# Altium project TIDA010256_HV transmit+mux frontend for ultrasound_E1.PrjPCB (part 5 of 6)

## Sheet 21_TX7516_PartBPinout.SchDoc
size 431 x 279 mm; Date: Not shown in title block; ApprovedBy: Not shown in title block; CheckedBy: Not shown in title block; Author: Not shown in title block; CompanyName: Not shown in title block; Engineer: Not shown in title block; Organization: Not shown in title block; Address1: Not shown in title block; Address2: Not shown in title block; Address3: Not shown in title block; Address4: Not shown in title block; DocumentNumber: 13; Revision: Use project parameter SCH_Rev; SheetNumber: 13; SheetTotal: 18; PageSetup: Record=PageOptions¦CenterHorizontal=True¦CenterVertical=True¦PrintScale=1.00¦XCorrection=1.00¦YCorrection=1.00¦PrintKind=0¦BorderSize=5000000¦LeftOffset=0¦BottomOffset=0¦Orientation=2¦PaperLength=1000¦PaperWidth=1000¦Scale=100¦PaperSource=15¦PrintQuality=600¦MediaType=1¦DitherType=10¦PaperKind=Letter¦PrintScaleMode=1
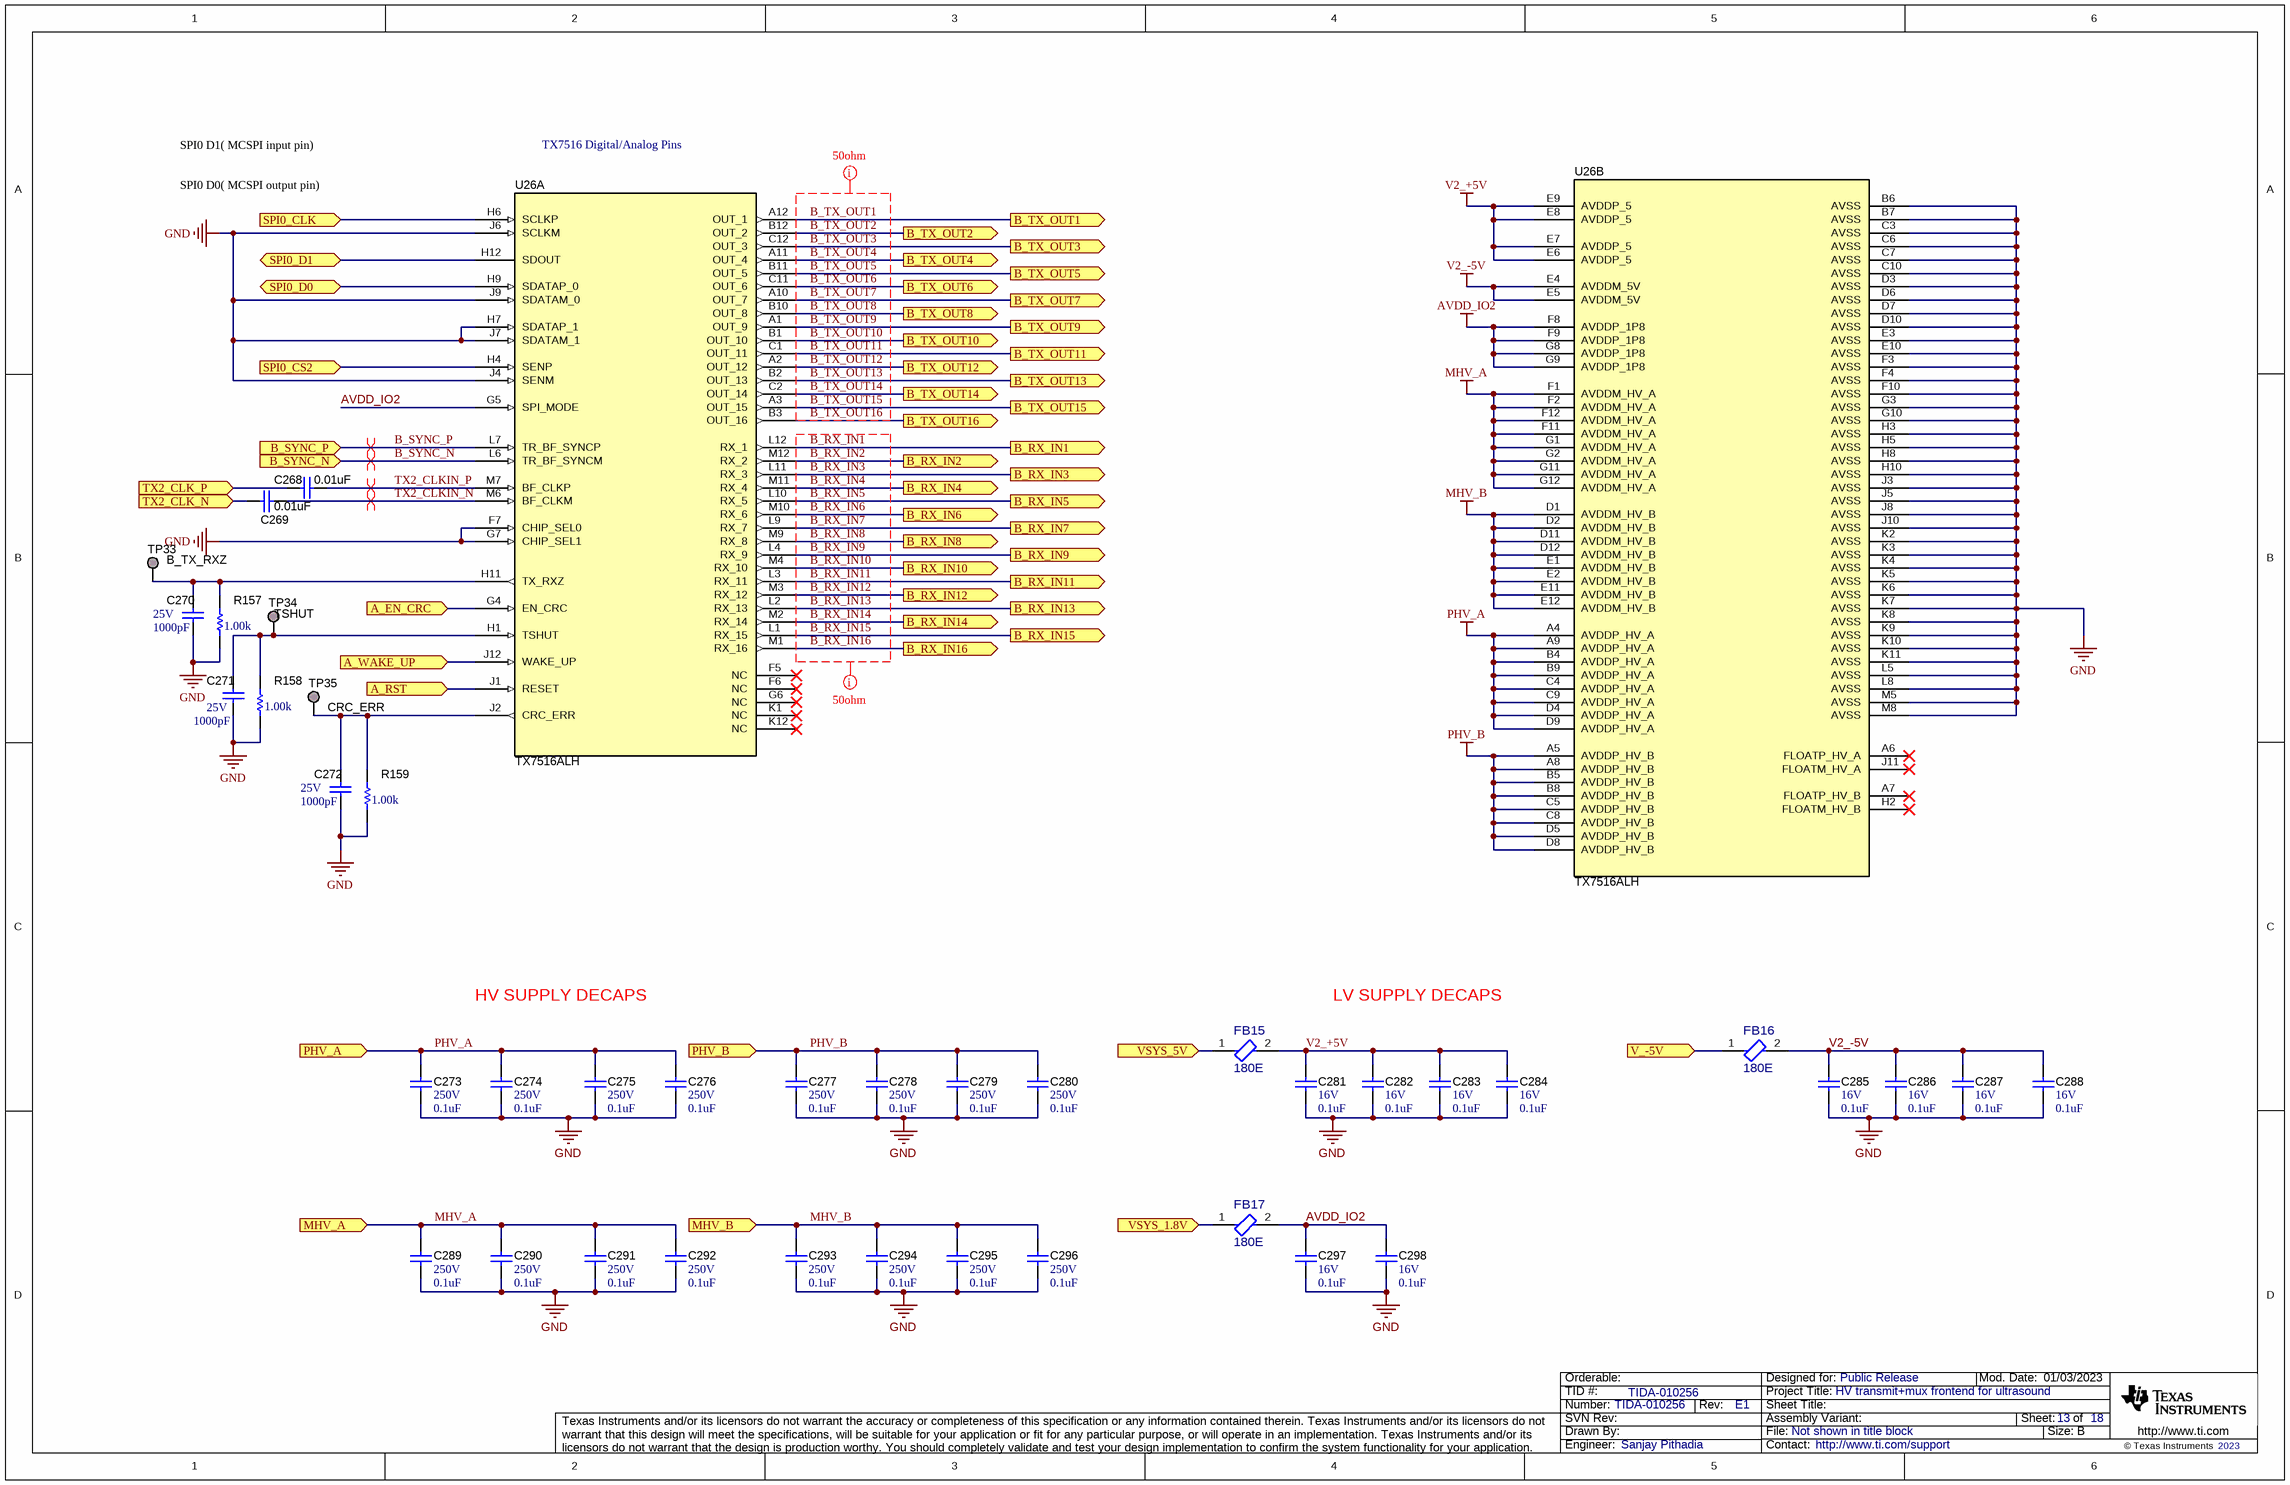
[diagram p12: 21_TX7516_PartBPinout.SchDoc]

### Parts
C268  ValueDisplayed: 0.01uF  [0402_065]  (hidden comment: 520L103KT16T)
C269  ValueDisplayed: 0.01uF  [0402_065]  (hidden comment: 520L103KT16T)
C270  VDC_V: 25V  ValueDisplayed: 1000pF  [0603]  (hidden comment: C0603C102K3GACTU)
C271  VDC_V: 25V  ValueDisplayed: 1000pF  [0603]  (hidden comment: C0603C102K3GACTU)
C272  VDC_V: 25V  ValueDisplayed: 1000pF  [0603]  (hidden comment: C0603C102K3GACTU)
C273  VDC_V: 250V  ValueDisplayed: 0.1uF  [0805_HV]  (hidden comment: C2012X7T2E104K125AA)
C274  VDC_V: 250V  ValueDisplayed: 0.1uF  [0805_HV]  (hidden comment: C2012X7T2E104K125AA)
C275  VDC_V: 250V  ValueDisplayed: 0.1uF  [0805_HV]  (hidden comment: C2012X7T2E104K125AA)
C276  VDC_V: 250V  ValueDisplayed: 0.1uF  [0805_HV]  (hidden comment: C2012X7T2E104K125AA)
C277  VDC_V: 250V  ValueDisplayed: 0.1uF  [0805_HV]  (hidden comment: C2012X7T2E104K125AA)
C278  VDC_V: 250V  ValueDisplayed: 0.1uF  [0805_HV]  (hidden comment: C2012X7T2E104K125AA)
C279  VDC_V: 250V  ValueDisplayed: 0.1uF  [0805_HV]  (hidden comment: C2012X7T2E104K125AA)
C280  VDC_V: 250V  ValueDisplayed: 0.1uF  [0805_HV]  (hidden comment: C2012X7T2E104K125AA)
C281  VDC_V: 16V  ValueDisplayed: 0.1uF  [0201_033]  (hidden comment: C0603X6S1C104K030BC)
C282  VDC_V: 16V  ValueDisplayed: 0.1uF  [0201_033]  (hidden comment: C0603X6S1C104K030BC)
C283  VDC_V: 16V  ValueDisplayed: 0.1uF  [0201_033]  (hidden comment: C0603X6S1C104K030BC)
C284  VDC_V: 16V  ValueDisplayed: 0.1uF  [0201_033]  (hidden comment: C0603X6S1C104K030BC)
C285  VDC_V: 16V  ValueDisplayed: 0.1uF  [0201_033]  (hidden comment: C0603X6S1C104K030BC)
C286  VDC_V: 16V  ValueDisplayed: 0.1uF  [0201_033]  (hidden comment: C0603X6S1C104K030BC)
C287  VDC_V: 16V  ValueDisplayed: 0.1uF  [0201_033]  (hidden comment: C0603X6S1C104K030BC)
C288  VDC_V: 16V  ValueDisplayed: 0.1uF  [0201_033]  (hidden comment: C0603X6S1C104K030BC)
C289  VDC_V: 250V  ValueDisplayed: 0.1uF  [0805_HV]  (hidden comment: C2012X7T2E104K125AA)
C290  VDC_V: 250V  ValueDisplayed: 0.1uF  [0805_HV]  (hidden comment: C2012X7T2E104K125AA)
C291  VDC_V: 250V  ValueDisplayed: 0.1uF  [0805_HV]  (hidden comment: C2012X7T2E104K125AA)
C292  VDC_V: 250V  ValueDisplayed: 0.1uF  [0805_HV]  (hidden comment: C2012X7T2E104K125AA)
C293  VDC_V: 250V  ValueDisplayed: 0.1uF  [0805_HV]  (hidden comment: C2012X7T2E104K125AA)
C294  VDC_V: 250V  ValueDisplayed: 0.1uF  [0805_HV]  (hidden comment: C2012X7T2E104K125AA)
C295  VDC_V: 250V  ValueDisplayed: 0.1uF  [0805_HV]  (hidden comment: C2012X7T2E104K125AA)
C296  VDC_V: 250V  ValueDisplayed: 0.1uF  [0805_HV]  (hidden comment: C2012X7T2E104K125AA)
C297  VDC_V: 16V  ValueDisplayed: 0.1uF  [0201_033]  (hidden comment: C0603X6S1C104K030BC)
C298  VDC_V: 16V  ValueDisplayed: 0.1uF  [0201_033]  (hidden comment: C0603X6S1C104K030BC)
FB15  180E  [FP-MPZ1608S181ATAH0_0603-MFG]
FB16  180E  [FP-MPZ1608S181ATAH0_0603-MFG]
FB17  180E  [FP-MPZ1608S181ATAH0_0603-MFG]
R157  ValueDisplayed: 1.00k  [0603]  (hidden comment: RC0603FR-071KL)
R158  ValueDisplayed: 1.00k  [0603]  (hidden comment: RC0603FR-071KL)
R159  ValueDisplayed: 1.00k  [0603]  (hidden comment: RC0603FR-071KL)
TP33  B_TX_RXZ  [TP_SM_1MM]  (no BOM)
TP34  TSHUT  [TP_SM_1MM]  (no BOM)
TP35  CRC_ERR  [TP_SM_1MM]  (no BOM)
U26  TX7516ALH  [ALH0144A]  (parts A,B of 2)

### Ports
A_EN_CRC (in), A_RST (in), A_WAKE_UP (in), B_RX_IN1 (out), B_RX_IN2 (out), B_RX_IN3 (out), B_RX_IN4 (out), B_RX_IN5 (out), B_RX_IN6 (out), B_RX_IN7 (out), B_RX_IN8 (out), B_RX_IN9 (out), B_RX_IN10 (out), B_RX_IN11 (out), B_RX_IN12 (out), B_RX_IN13 (out), B_RX_IN14 (out), B_RX_IN15 (out), B_RX_IN16 (out), B_SYNC_N (in), B_SYNC_P (in), B_TX_OUT1 (out), B_TX_OUT2 (out), B_TX_OUT3 (out), B_TX_OUT4 (out), B_TX_OUT5 (out), B_TX_OUT6 (out), B_TX_OUT7 (out), B_TX_OUT8 (out), B_TX_OUT9 (out), B_TX_OUT10 (out), B_TX_OUT11 (out), B_TX_OUT12 (out), B_TX_OUT13 (out), B_TX_OUT14 (out), B_TX_OUT15 (out), B_TX_OUT16 (out), MHV_A (in), MHV_B (in), PHV_A (in), PHV_B (in), SPI0_CLK (in), SPI0_CS2 (in), SPI0_D0 (bidir), SPI0_D1 (bidir), TX2_CLK_N (in), TX2_CLK_P (in), V_-5V (in), VSYS_1.8V (in), VSYS_5V (in)

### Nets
AVDD_IO2: C297.1 C298.1 FB17.2 U26.F8(AVDDP_1P8) U26.F9(AVDDP_1P8) U26.G5(SPI_MODE) U26.G8(AVDDP_1P8) U26.G9(AVDDP_1P8)
GND: C270.2 C271.2 C272.2 C273.2 C274.2 C275.2 C276.2 C277.2 C278.2 C279.2 C280.2 C281.2 C282.2 C283.2 C284.2 C285.2 C286.2 C287.2 C288.2 C289.2 C290.2 C291.2 C292.2 C293.2 C294.2 C295.2 C296.2 C297.2 C298.2 R157.1 R158.1 R159.1 U26.B6(AVSS) U26.B7(AVSS) U26.C3(AVSS) U26.C6(AVSS) U26.C7(AVSS) U26.C10(AVSS) U26.D3(AVSS) U26.D6(AVSS) U26.D7(AVSS) U26.D10(AVSS) U26.E3(AVSS) U26.E10(AVSS) U26.F3(AVSS) U26.F4(AVSS) U26.F7(CHIP_SEL0) U26.F10(AVSS) U26.G3(AVSS) U26.G7(CHIP_SEL1) U26.G10(AVSS) U26.H3(AVSS) U26.H5(AVSS) U26.H7(SDATAP_1) U26.H8(AVSS) U26.H10(AVSS) U26.J3(AVSS) U26.J4(SENM) U26.J5(AVSS) U26.J6(SCLKM) U26.J7(SDATAM_1) U26.J8(AVSS) U26.J9(SDATAM_0) U26.J10(AVSS) U26.K2(AVSS) U26.K3(AVSS) U26.K4(AVSS) U26.K5(AVSS) U26.K6(AVSS) U26.K7(AVSS) U26.K8(AVSS) U26.K9(AVSS) U26.K10(AVSS) U26.K11(AVSS) U26.L5(AVSS) U26.L8(AVSS) U26.M5(AVSS) U26.M8(AVSS)
MHV_A: C289.1 C290.1 C291.1 C292.1 U26.F1(AVDDM_HV_A) U26.F2(AVDDM_HV_A) U26.F11(AVDDM_HV_A) U26.F12(AVDDM_HV_A) U26.G1(AVDDM_HV_A) U26.G2(AVDDM_HV_A) U26.G11(AVDDM_HV_A) U26.G12(AVDDM_HV_A) ; port MHV_A
MHV_B: C293.1 C294.1 C295.1 C296.1 U26.D1(AVDDM_HV_B) U26.D2(AVDDM_HV_B) U26.D11(AVDDM_HV_B) U26.D12(AVDDM_HV_B) U26.E1(AVDDM_HV_B) U26.E2(AVDDM_HV_B) U26.E11(AVDDM_HV_B) U26.E12(AVDDM_HV_B) ; port MHV_B
PHV_A: C273.1 C274.1 C275.1 C276.1 U26.A4(AVDDP_HV_A) U26.A9(AVDDP_HV_A) U26.B4(AVDDP_HV_A) U26.B9(AVDDP_HV_A) U26.C4(AVDDP_HV_A) U26.C9(AVDDP_HV_A) U26.D4(AVDDP_HV_A) U26.D9(AVDDP_HV_A) ; port PHV_A
PHV_B: C277.1 C278.1 C279.1 C280.1 U26.A5(AVDDP_HV_B) U26.A8(AVDDP_HV_B) U26.B5(AVDDP_HV_B) U26.B8(AVDDP_HV_B) U26.C5(AVDDP_HV_B) U26.C8(AVDDP_HV_B) U26.D5(AVDDP_HV_B) U26.D8(AVDDP_HV_B) ; port PHV_B
V2_+5V: C281.1 C282.1 C283.1 C284.1 FB15.2 U26.E6(AVDDP_5) U26.E7(AVDDP_5) U26.E8(AVDDP_5) U26.E9(AVDDP_5)
V2_-5V: C285.1 C286.1 C287.1 C288.1 FB16.2 U26.E4(AVDDM_5V) U26.E5(AVDDM_5V)
B_RX_IN1: U26.L12(RX_1) ; port B_RX_IN1
B_RX_IN2: U26.M12(RX_2) ; port B_RX_IN2
B_RX_IN3: U26.L11(RX_3) ; port B_RX_IN3
B_RX_IN4: U26.M11(RX_4) ; port B_RX_IN4
B_RX_IN5: U26.L10(RX_5) ; port B_RX_IN5
B_RX_IN6: U26.M10(RX_6) ; port B_RX_IN6
B_RX_IN7: U26.L9(RX_7) ; port B_RX_IN7
B_RX_IN8: U26.M9(RX_8) ; port B_RX_IN8
B_RX_IN9: U26.L4(RX_9) ; port B_RX_IN9
B_RX_IN10: U26.M4(RX_10) ; port B_RX_IN10
B_RX_IN11: U26.L3(RX_11) ; port B_RX_IN11
B_RX_IN12: U26.M3(RX_12) ; port B_RX_IN12
B_RX_IN13: U26.L2(RX_13) ; port B_RX_IN13
B_RX_IN14: U26.M2(RX_14) ; port B_RX_IN14
B_RX_IN15: U26.L1(RX_15) ; port B_RX_IN15
B_RX_IN16: U26.M1(RX_16) ; port B_RX_IN16
B_SYNC_N: U26.L6(TR_BF_SYNCM) ; port B_SYNC_N
B_SYNC_P: U26.L7(TR_BF_SYNCP) ; port B_SYNC_P
B_TX_OUT1: U26.A12(OUT_1) ; port B_TX_OUT1
B_TX_OUT2: U26.B12(OUT_2) ; port B_TX_OUT2
B_TX_OUT3: U26.C12(OUT_3) ; port B_TX_OUT3
B_TX_OUT4: U26.A11(OUT_4) ; port B_TX_OUT4
B_TX_OUT5: U26.B11(OUT_5) ; port B_TX_OUT5
B_TX_OUT6: U26.C11(OUT_6) ; port B_TX_OUT6
B_TX_OUT7: U26.A10(OUT_7) ; port B_TX_OUT7
B_TX_OUT8: U26.B10(OUT_8) ; port B_TX_OUT8
B_TX_OUT9: U26.A1(OUT_9) ; port B_TX_OUT9
B_TX_OUT10: U26.B1(OUT_10) ; port B_TX_OUT10
B_TX_OUT11: U26.C1(OUT_11) ; port B_TX_OUT11
B_TX_OUT12: U26.A2(OUT_12) ; port B_TX_OUT12
B_TX_OUT13: U26.B2(OUT_13) ; port B_TX_OUT13
B_TX_OUT14: U26.C2(OUT_14) ; port B_TX_OUT14
B_TX_OUT15: U26.A3(OUT_15) ; port B_TX_OUT15
B_TX_OUT16: U26.B3(OUT_16) ; port B_TX_OUT16
TX2_CLK_N: C269.2 ; port TX2_CLK_N
TX2_CLK_P: C268.2 ; port TX2_CLK_P
TX2_CLKIN_N: C269.1 U26.M6(BF_CLKM)
TX2_CLKIN_P: C268.1 U26.M7(BF_CLKP)
V_-5V: FB16.1 ; port V_-5V
VSYS_1.8V: FB17.1 ; port VSYS_1.8V
VSYS_5V: FB15.1 ; port VSYS_5V
NetC270_1: C270.1 R157.2 TP33.1 U26.H11(TX_RXZ)
NetC271_1: C271.1 R158.2 TP34.1 U26.H1(TSHUT)
NetC272_1: C272.1 R159.2 TP35.1 U26.J2(CRC_ERR)
NetR514_2: U26.H4(SENP) ; port SPI0_CS2
NetU17_A8: U26.H9(SDATAP_0) ; port SPI0_D0
NetU17_A17: U26.J12(WAKE_UP) ; port A_WAKE_UP
NetU17_B8: U26.H6(SCLKP) ; port SPI0_CLK
NetU17_B15: U26.G4(EN_CRC) ; port A_EN_CRC
NetU17_B16: U26.J1(RESET) ; port A_RST
NetU17_C9: U26.H12(SDOUT) ; port SPI0_D1

Not connected (* = marked no-connect by the designer): U26 A6(FLOATP_HV_A)* A7(FLOATP_HV_B)* F5(NC)* F6(NC)* G6(NC)* H2(FLOATM_HV_B)* J11(FLOATM_HV_A)* K1(NC)* K12(NC)*

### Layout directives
differential pair; differential pair class 100ohm: B_SYNC_N, B_SYNC_P, TX2_CLKIN_N, TX2_CLKIN_P
net class B_TX_OUT: B_TX_OUT1, B_TX_OUT2, B_TX_OUT3, B_TX_OUT4, B_TX_OUT5, B_TX_OUT6, B_TX_OUT7, B_TX_OUT8, B_TX_OUT9, B_TX_OUT10, B_TX_OUT11, B_TX_OUT12, B_TX_OUT13, B_TX_OUT14, B_TX_OUT15, B_TX_OUT16
net class B_RX_IN: B_RX_IN1, B_RX_IN2, B_RX_IN3, B_RX_IN4, B_RX_IN5, B_RX_IN6, B_RX_IN7, B_RX_IN8, B_RX_IN9, B_RX_IN10, B_RX_IN11, B_RX_IN12, B_RX_IN13, B_RX_IN14, B_RX_IN15, B_RX_IN16

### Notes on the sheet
- SPI0 D1( MCSPI input pin)
- TX7516 Digital/Analog Pins
- SPI0 D0( MCSPI output pin)
- HV SUPPLY DECAPS
- LV SUPPLY DECAPS

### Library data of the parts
C268 C269 = CMP-0006210-2: CAP, CERM, 0.01 uF, 16 V, +/- 10%, X7R, 0402; Manufacturer: AT Ceramics; TaMin_C: -55°C; Polarized: N; SizeAreaWB_mm2: 3; Value1: Unknown; U/M: EA; Value: 0.01uF; TaMax_C: 125°C; SizeZ_mm: 0.65; SizeX_mm: 1; SizeY_mm: 0.5; Cap_Case: 0402; Value2: 16V; CompType: Capacitor; Cap_F: 10nF; AEC Category: Q200
C270-C272 = CMP-0006846-4: CAP, CERM, 1000 pF, 25 V, +/- 10%, C0G/NP0, 0603; Manufacturer: Kemet; TaMin_C: -55°C; ESR_ohm: 0; Polarized: N; SizeAreaWB_mm2: 4.68; Value1: 0 ohm; U/M: EA; Value: 1000pF; TaMax_C: 125°C; SizeZ_mm: 1; SizeX_mm: 1.6; SizeY_mm: 0.8; SizeArea_mm2: 1.28; Cap_F: 1nF; IRMS_A: 0A; AEC Category: Q200
C273-C280 C289-C296 = CMP-0007897-1: CAP, CERM, 0.1 uF, 250 V, +/- 10%, X7T, 0805; Manufacturer: TDK; TaMin_C: -55°C; Polarized: N; SizeAreaWB_mm2: 6.75; Value1: Unknown; U/M: EA; Value: 0.1uF; TaMax_C: 125°C; SizeZ_mm: 1.45; SizeX_mm: 2; SizeY_mm: 1.25; Cap_Case: 0805; SizeArea_mm2: 2.5; Cap_F: 100nF; AEC Category: Q200
C281-C288 C297 C298 = CMP-0009637-3: CAP, CERM, 0.1 uF, 16 V, +/- 10%, X6S, 0201; Manufacturer: TDK; TaMin_C: -55°C; Polarized: N; SizeAreaWB_mm2: 2.08; Value1: Unknown; U/M: EA; Value: 0.1uF; TaMax_C: 105°C; SizeZ_mm: 0.33; SizeX_mm: 0.6; SizeY_mm: 0.3; Cap_Case: 0201; SizeArea_mm2: 0.18; Cap_F: 100nF; AEC Category: Q200
FB15-FB17 = CMP-0092257-1: 180 Ohms @ 100MHz 1 Power Line Ferrite Bead 0603 (1608 Metric) 2A 50mOhm; PartNumber: MPZ1608S181ATAH0; Manufacturer: TDK Corporation; SizeZ_mm: 0.75mm; Tolerance_%: 25%; AEC Qualified: No; Impedance At Frequency: 180Ω @ 100MHz; DCR_ohm: 50m
R157-R159 = CMP-0022895-5: RES, 1.00 k, 1%, 0.1 W, 0603; Manufacturer: Yageo; Power_W: 100mW; TempCo: 100 ppm/C; Value_Code: 1k00; Value: 1.00k; EIA_Code: E96; Res_ohm: 1k; SizeX_mm: 1.6; SizeY_mm: 0.8; SizeZ_mm: 1; Value2: 0.1W; SizeArea_mm2: 1.28; AEC Qualified: N; VDC_V: 75V; AEC Category: Q200; SizeAreaWB_mm2: 4.68
TP33-TP35 = CMP-0003825-1: 1mm Test Point, SMT; Manufacturer: Any
U26 = CMP-0860806-2: Five-Level, 16-Channel Transmitter with T/R Switch, and On-Chip Beamformer, ALH0144A (FCBGA-144); Manufacturer: Texas Instruments; SizeZ_mm: 1.321; SizeArea_mm2: 100; SizeY_mm: 10; AEC Qualified: N; AEC Category: Q200; CompType: IC; SizeAreaWB_mm2: 144

## Sheet 22_TMUX9832(0-64)_Pinout.SchDoc
size 431 x 279 mm; Date: Not shown in title block; ApprovedBy: Not shown in title block; CheckedBy: Not shown in title block; Author: Not shown in title block; CompanyName: Not shown in title block; Engineer: Not shown in title block; Organization: Not shown in title block; Address1: Not shown in title block; Address2: Not shown in title block; Address3: Not shown in title block; Address4: Not shown in title block; DocumentNumber: 14; Revision: Use project parameter SCH_Rev; SheetNumber: 14; SheetTotal: 18; PageSetup: Record=PageOptions¦CenterHorizontal=True¦CenterVertical=True¦PrintScale=1.00¦XCorrection=1.00¦YCorrection=1.00¦PrintKind=0¦BorderSize=5000000¦LeftOffset=0¦BottomOffset=0¦Orientation=2¦PaperLength=1000¦PaperWidth=1000¦Scale=100¦PaperSource=15¦PrintQuality=600¦MediaType=1¦DitherType=10¦PaperKind=Letter¦PrintScaleMode=1
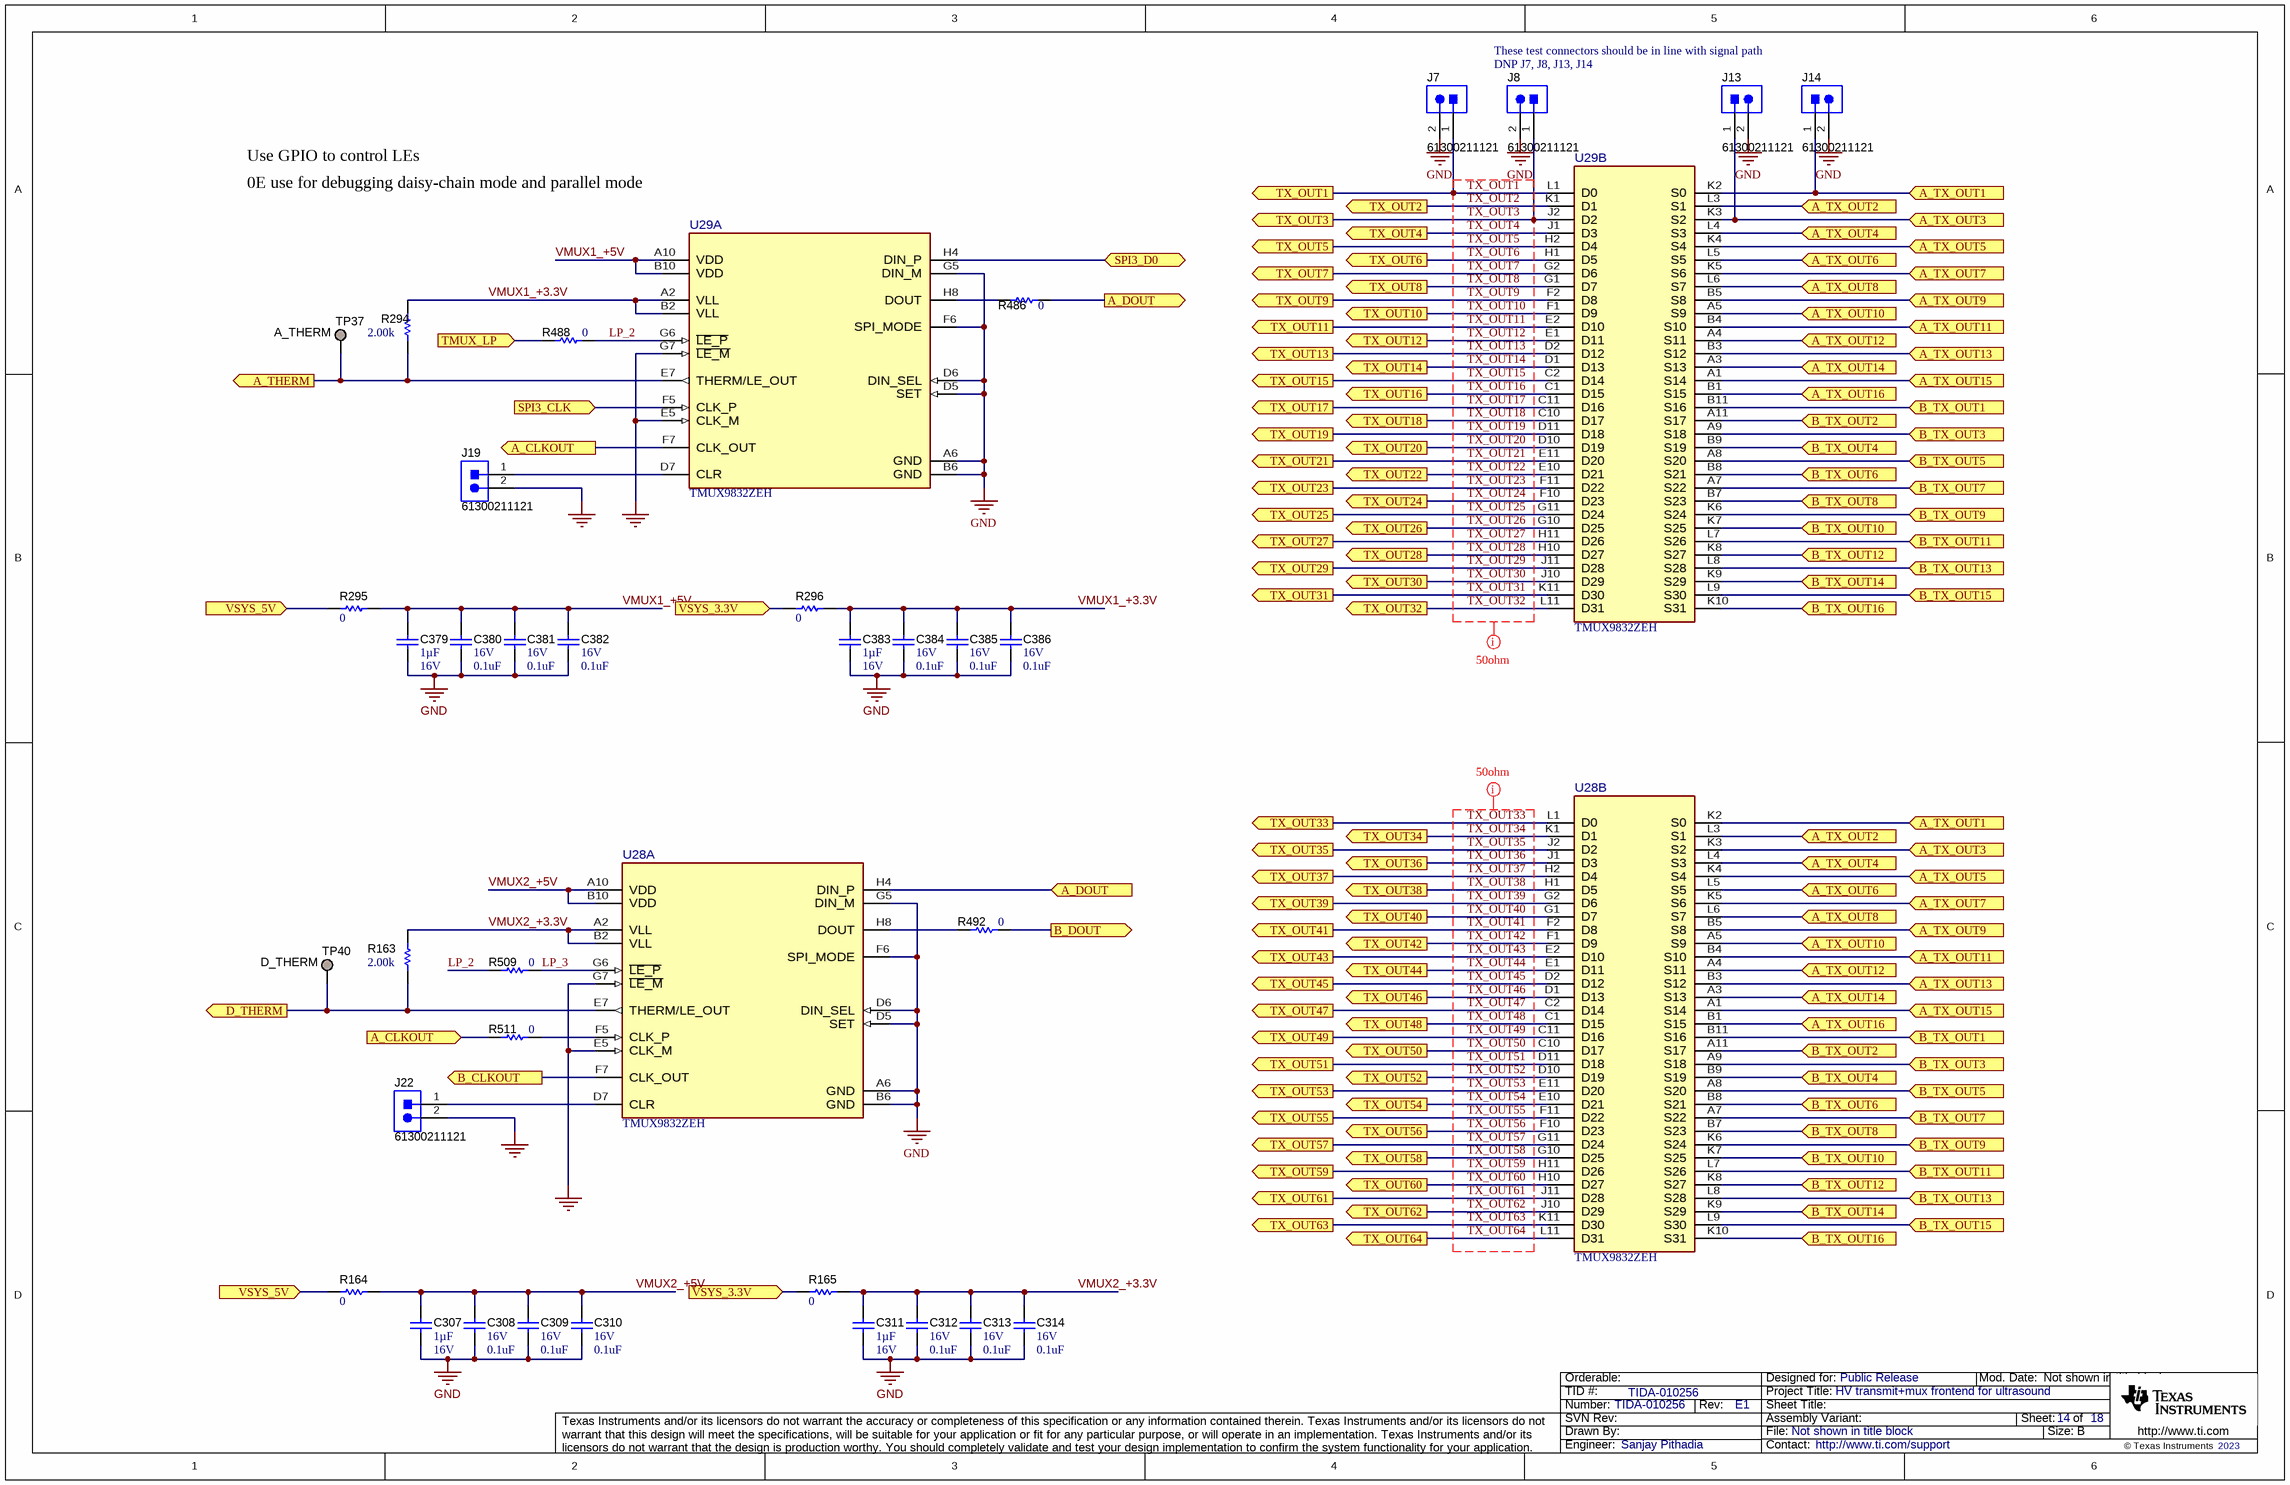
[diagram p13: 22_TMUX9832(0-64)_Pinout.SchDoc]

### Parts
C307  Cap_F: 1µF  VDC_V: 16V  [0805_HV]  (hidden comment: C0805C105K4RACAUTO)
C308  VDC_V: 16V  ValueDisplayed: 0.1uF  [0201_033]  (hidden comment: C0603X6S1C104K030BC)
C309  VDC_V: 16V  ValueDisplayed: 0.1uF  [0201_033]  (hidden comment: C0603X6S1C104K030BC)
C310  VDC_V: 16V  ValueDisplayed: 0.1uF  [0201_033]  (hidden comment: C0603X6S1C104K030BC)
C311  Cap_F: 1µF  VDC_V: 16V  [0805_HV]  (hidden comment: C0805C105K4RACAUTO)
C312  VDC_V: 16V  ValueDisplayed: 0.1uF  [0201_033]  (hidden comment: C0603X6S1C104K030BC)
C313  VDC_V: 16V  ValueDisplayed: 0.1uF  [0201_033]  (hidden comment: C0603X6S1C104K030BC)
C314  VDC_V: 16V  ValueDisplayed: 0.1uF  [0201_033]  (hidden comment: C0603X6S1C104K030BC)
C379  Cap_F: 1µF  VDC_V: 16V  [0805_HV]  (hidden comment: C0805C105K4RACAUTO)
C380  VDC_V: 16V  ValueDisplayed: 0.1uF  [0201_033]  (hidden comment: C0603X6S1C104K030BC)
C381  VDC_V: 16V  ValueDisplayed: 0.1uF  [0201_033]  (hidden comment: C0603X6S1C104K030BC)
C382  VDC_V: 16V  ValueDisplayed: 0.1uF  [0201_033]  (hidden comment: C0603X6S1C104K030BC)
C383  Cap_F: 1µF  VDC_V: 16V  [0805_HV]  (hidden comment: C0805C105K4RACAUTO)
C384  VDC_V: 16V  ValueDisplayed: 0.1uF  [0201_033]  (hidden comment: C0603X6S1C104K030BC)
C385  VDC_V: 16V  ValueDisplayed: 0.1uF  [0201_033]  (hidden comment: C0603X6S1C104K030BC)
C386  VDC_V: 16V  ValueDisplayed: 0.1uF  [0201_033]  (hidden comment: C0603X6S1C104K030BC)
J7  61300211121  [WURTH_61300211121]
J8  61300211121  [WURTH_61300211121]
J13  61300211121  [WURTH_61300211121]
J14  61300211121  [WURTH_61300211121]
J19  61300211121  [WURTH_61300211121]
J22  61300211121  [WURTH_61300211121]
R163  ValueDisplayed: 2.00k  [0603]  (hidden comment: ERJ3EKF2001V)
R164  ValueDisplayed: 0  [0603]  (hidden comment: ERJ-L03KF10CV)
R165  ValueDisplayed: 0  [0603]  (hidden comment: ERJ-L03KF10CV)
R294  ValueDisplayed: 2.00k  [0603]  (hidden comment: ERJ3EKF2001V)
R295  ValueDisplayed: 0  [0603]  (hidden comment: ERJ-L03KF10CV)
R296  ValueDisplayed: 0  [0603]  (hidden comment: ERJ-L03KF10CV)
R486  ValueDisplayed: 0  [0603]  (hidden comment: ERJ-3GEY0R00V)
R488  ValueDisplayed: 0  [0603]  (hidden comment: ERJ-3GEY0R00V)
R492  ValueDisplayed: 0  [0603]  (hidden comment: ERJ-3GEY0R00V)
R509  ValueDisplayed: 0  [0603]  (hidden comment: ERJ-3GEY0R00V)
R511  ValueDisplayed: 0  [0603]  (hidden comment: ERJ-3GEY0R00V)
TP37  A_THERM  [TP_SM_1MM]  (no BOM)
TP40  D_THERM  [TP_SM_1MM]  (no BOM)
U28  TMUX9832ZEH  [ZEH0083A-MFG]  (parts A,B of 2)
U29  TMUX9832ZEH  [ZEH0083A-MFG]  (parts A,B of 2)

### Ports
A_CLKOUT (in), A_CLKOUT (out), A_DOUT (in), A_DOUT (out), A_THERM (out), A_TX_OUT1 (in), A_TX_OUT2 (in), A_TX_OUT3 (in), A_TX_OUT4 (in), A_TX_OUT5 (in), A_TX_OUT6 (in), A_TX_OUT7 (in), A_TX_OUT8 (in), A_TX_OUT9 (in), A_TX_OUT10 (in), A_TX_OUT11 (in), A_TX_OUT12 (in), A_TX_OUT13 (in), A_TX_OUT14 (in), A_TX_OUT15 (in), A_TX_OUT16 (in), B_CLKOUT (out), B_DOUT (out), B_TX_OUT1 (in), B_TX_OUT2 (in), B_TX_OUT3 (in), B_TX_OUT4 (in), B_TX_OUT5 (in), B_TX_OUT6 (in), B_TX_OUT7 (in), B_TX_OUT8 (in), B_TX_OUT9 (in), B_TX_OUT10 (in), B_TX_OUT11 (in), B_TX_OUT12 (in), B_TX_OUT13 (in), B_TX_OUT14 (in), B_TX_OUT15 (in), B_TX_OUT16 (in), D_THERM (out), SPI3_CLK (in), SPI3_D0 (bidir), TMUX_LP (in), TX_OUT1 (out), TX_OUT2 (out), TX_OUT3 (out), TX_OUT4 (out), TX_OUT5 (out), TX_OUT6 (out), TX_OUT7 (out), TX_OUT8 (out), TX_OUT9 (out), TX_OUT10 (out), TX_OUT11 (out), TX_OUT12 (out), TX_OUT13 (out), TX_OUT14 (out), TX_OUT15 (out), TX_OUT16 (out), TX_OUT17 (out), TX_OUT18 (out), TX_OUT19 (out), TX_OUT20 (out), TX_OUT21 (out), TX_OUT22 (out), TX_OUT23 (out), TX_OUT24 (out), TX_OUT25 (out), TX_OUT26 (out), TX_OUT27 (out), TX_OUT28 (out), TX_OUT29 (out), TX_OUT30 (out), TX_OUT31 (out), TX_OUT32 (out), TX_OUT33 (out), TX_OUT34 (out), TX_OUT35 (out), TX_OUT36 (out), TX_OUT37 (out), TX_OUT38 (out), TX_OUT39 (out), TX_OUT40 (out), TX_OUT41 (out), TX_OUT42 (out), TX_OUT43 (out), TX_OUT44 (out), TX_OUT45 (out), TX_OUT46 (out), TX_OUT47 (out), TX_OUT48 (out), TX_OUT49 (out), TX_OUT50 (out), TX_OUT51 (out), TX_OUT52 (out), TX_OUT53 (out), TX_OUT54 (out), TX_OUT55 (out), TX_OUT56 (out), TX_OUT57 (out), TX_OUT58 (out), TX_OUT59 (out), TX_OUT60 (out), TX_OUT61 (out), TX_OUT62 (out), TX_OUT63 (out), TX_OUT64 (out), VSYS_3.3V (in), VSYS_5V (in)

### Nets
GND: C307.2 C308.2 C309.2 C310.2 C311.2 C312.2 C313.2 C314.2 C379.2 C380.2 C381.2 C382.2 C383.2 C384.2 C385.2 C386.2 J7.2 J8.2 J13.2 J14.2 J19.2 J22.2 U28.A6(GND) U28.B6(GND) U28.D5(SET) U28.D6(DIN_SEL) U28.E5(CLK_M) U28.F6(SPI_MODE) U28.G5(DIN_M) U28.G7(~{LE_M}) U29.A6(GND) U29.B6(GND) U29.D5(SET) U29.D6(DIN_SEL) U29.E5(CLK_M) U29.F6(SPI_MODE) U29.G5(DIN_M) U29.G7(~{LE_M})
A_TX_OUT1: J14.1 U28.K2(S0) U29.K2(S0) ; port A_TX_OUT1
A_TX_OUT2: U28.L3(S1) U29.L3(S1) ; port A_TX_OUT2
A_TX_OUT3: J13.1 U28.K3(S2) U29.K3(S2) ; port A_TX_OUT3
A_TX_OUT4: U28.L4(S3) U29.L4(S3) ; port A_TX_OUT4
A_TX_OUT5: U28.K4(S4) U29.K4(S4) ; port A_TX_OUT5
A_TX_OUT6: U28.L5(S5) U29.L5(S5) ; port A_TX_OUT6
A_TX_OUT7: U28.K5(S6) U29.K5(S6) ; port A_TX_OUT7
A_TX_OUT8: U28.L6(S7) U29.L6(S7) ; port A_TX_OUT8
A_TX_OUT9: U28.B5(S8) U29.B5(S8) ; port A_TX_OUT9
A_TX_OUT10: U28.A5(S9) U29.A5(S9) ; port A_TX_OUT10
A_TX_OUT11: U28.B4(S10) U29.B4(S10) ; port A_TX_OUT11
A_TX_OUT12: U28.A4(S11) U29.A4(S11) ; port A_TX_OUT12
A_TX_OUT13: U28.B3(S12) U29.B3(S12) ; port A_TX_OUT13
A_TX_OUT14: U28.A3(S13) U29.A3(S13) ; port A_TX_OUT14
A_TX_OUT15: U28.A1(S14) U29.A1(S14) ; port A_TX_OUT15
A_TX_OUT16: U28.B1(S15) U29.B1(S15) ; port A_TX_OUT16
B_TX_OUT1: U28.B11(S16) U29.B11(S16) ; port B_TX_OUT1
B_TX_OUT2: U28.A11(S17) U29.A11(S17) ; port B_TX_OUT2
B_TX_OUT3: U28.A9(S18) U29.A9(S18) ; port B_TX_OUT3
B_TX_OUT4: U28.B9(S19) U29.B9(S19) ; port B_TX_OUT4
B_TX_OUT5: U28.A8(S20) U29.A8(S20) ; port B_TX_OUT5
B_TX_OUT6: U28.B8(S21) U29.B8(S21) ; port B_TX_OUT6
B_TX_OUT7: U28.A7(S22) U29.A7(S22) ; port B_TX_OUT7
B_TX_OUT8: U28.B7(S23) U29.B7(S23) ; port B_TX_OUT8
B_TX_OUT9: U28.K6(S24) U29.K6(S24) ; port B_TX_OUT9
B_TX_OUT10: U28.K7(S25) U29.K7(S25) ; port B_TX_OUT10
B_TX_OUT11: U28.L7(S26) U29.L7(S26) ; port B_TX_OUT11
B_TX_OUT12: U28.K8(S27) U29.K8(S27) ; port B_TX_OUT12
B_TX_OUT13: U28.L8(S28) U29.L8(S28) ; port B_TX_OUT13
B_TX_OUT14: U28.K9(S29) U29.K9(S29) ; port B_TX_OUT14
B_TX_OUT15: U28.L9(S30) U29.L9(S30) ; port B_TX_OUT15
B_TX_OUT16: U28.K10(S31) U29.K10(S31) ; port B_TX_OUT16
LP_2: R488.2 R509.1 U29.G6(~{LE_P})
LP_3: R509.2 U28.G6(~{LE_P})
TX_OUT1: J7.1 U29.L1(D0) ; port TX_OUT1
TX_OUT2: U29.K1(D1) ; port TX_OUT2
TX_OUT3: J8.1 U29.J2(D2) ; port TX_OUT3
TX_OUT4: U29.J1(D3) ; port TX_OUT4
TX_OUT5: U29.H2(D4) ; port TX_OUT5
TX_OUT6: U29.H1(D5) ; port TX_OUT6
TX_OUT7: U29.G2(D6) ; port TX_OUT7
TX_OUT8: U29.G1(D7) ; port TX_OUT8
TX_OUT9: U29.F2(D8) ; port TX_OUT9
TX_OUT10: U29.F1(D9) ; port TX_OUT10
TX_OUT11: U29.E2(D10) ; port TX_OUT11
TX_OUT12: U29.E1(D11) ; port TX_OUT12
TX_OUT13: U29.D2(D12) ; port TX_OUT13
TX_OUT14: U29.D1(D13) ; port TX_OUT14
TX_OUT15: U29.C2(D14) ; port TX_OUT15
TX_OUT16: U29.C1(D15) ; port TX_OUT16
TX_OUT17: U29.C11(D16) ; port TX_OUT17
TX_OUT18: U29.C10(D17) ; port TX_OUT18
TX_OUT19: U29.D11(D18) ; port TX_OUT19
TX_OUT20: U29.D10(D19) ; port TX_OUT20
TX_OUT21: U29.E11(D20) ; port TX_OUT21
TX_OUT22: U29.E10(D21) ; port TX_OUT22
TX_OUT23: U29.F11(D22) ; port TX_OUT23
TX_OUT24: U29.F10(D23) ; port TX_OUT24
TX_OUT25: U29.G11(D24) ; port TX_OUT25
TX_OUT26: U29.G10(D25) ; port TX_OUT26
TX_OUT27: U29.H11(D26) ; port TX_OUT27
TX_OUT28: U29.H10(D27) ; port TX_OUT28
TX_OUT29: U29.J11(D28) ; port TX_OUT29
TX_OUT30: U29.J10(D29) ; port TX_OUT30
TX_OUT31: U29.K11(D30) ; port TX_OUT31
TX_OUT32: U29.L11(D31) ; port TX_OUT32
TX_OUT33: U28.L1(D0) ; port TX_OUT33
TX_OUT34: U28.K1(D1) ; port TX_OUT34
TX_OUT35: U28.J2(D2) ; port TX_OUT35
TX_OUT36: U28.J1(D3) ; port TX_OUT36
TX_OUT37: U28.H2(D4) ; port TX_OUT37
TX_OUT38: U28.H1(D5) ; port TX_OUT38
TX_OUT39: U28.G2(D6) ; port TX_OUT39
TX_OUT40: U28.G1(D7) ; port TX_OUT40
TX_OUT41: U28.F2(D8) ; port TX_OUT41
TX_OUT42: U28.F1(D9) ; port TX_OUT42
TX_OUT43: U28.E2(D10) ; port TX_OUT43
TX_OUT44: U28.E1(D11) ; port TX_OUT44
TX_OUT45: U28.D2(D12) ; port TX_OUT45
TX_OUT46: U28.D1(D13) ; port TX_OUT46
TX_OUT47: U28.C2(D14) ; port TX_OUT47
TX_OUT48: U28.C1(D15) ; port TX_OUT48
TX_OUT49: U28.C11(D16) ; port TX_OUT49
TX_OUT50: U28.C10(D17) ; port TX_OUT50
TX_OUT51: U28.D11(D18) ; port TX_OUT51
TX_OUT52: U28.D10(D19) ; port TX_OUT52
TX_OUT53: U28.E11(D20) ; port TX_OUT53
TX_OUT54: U28.E10(D21) ; port TX_OUT54
TX_OUT55: U28.F11(D22) ; port TX_OUT55
TX_OUT56: U28.F10(D23) ; port TX_OUT56
TX_OUT57: U28.G11(D24) ; port TX_OUT57
TX_OUT58: U28.G10(D25) ; port TX_OUT58
TX_OUT59: U28.H11(D26) ; port TX_OUT59
TX_OUT60: U28.H10(D27) ; port TX_OUT60
TX_OUT61: U28.J11(D28) ; port TX_OUT61
TX_OUT62: U28.J10(D29) ; port TX_OUT62
TX_OUT63: U28.K11(D30) ; port TX_OUT63
TX_OUT64: U28.L11(D31) ; port TX_OUT64
VMUX1_+3.3V: C383.1 C384.1 C385.1 C386.1 R294.2 R296.2 U29.A2(VLL) U29.B2(VLL)
VMUX1_+5V: C379.1 C380.1 C381.1 C382.1 R295.2 U29.A10(VDD) U29.B10(VDD)
VMUX2_+3.3V: C311.1 C312.1 C313.1 C314.1 R163.2 R165.2 U28.A2(VLL) U28.B2(VLL)
VMUX2_+5V: C307.1 C308.1 C309.1 C310.1 R164.2 U28.A10(VDD) U28.B10(VDD)
VSYS_3.3V: R165.1 R296.1 ; port VSYS_3.3V
VSYS_5V: R164.1 R295.1 ; port VSYS_5V
NetJ19_1: J19.1 U29.D7(CLR)
NetJ22_1: J22.1 U28.D7(CLR)
NetR163_1: R163.1 TP40.1 U28.E7(THERM/LE_OUT) ; port D_THERM
NetR294_1: R294.1 TP37.1 U29.E7(THERM/LE_OUT) ; port A_THERM
NetR486_1: R486.1 U29.H8(DOUT)
NetR486_2: R486.2 U28.H4(DIN_P) ; port A_DOUT
NetR488_1: R488.1 ; port TMUX_LP
NetR492_1: R492.1 U28.H8(DOUT)
NetR492_2: R492.2 ; port B_DOUT
NetR504_1: U28.F7(CLK_OUT) ; port B_CLKOUT
NetR511_1: R511.1 U29.F7(CLK_OUT) ; port A_CLKOUT
NetR511_2: R511.2 U28.F5(CLK_P)
NetU17_N1: U29.H4(DIN_P) ; port SPI3_D0
NetU17_N3: U29.F5(CLK_P) ; port SPI3_CLK

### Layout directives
net class U29B_TX_OUT_01_32: TX_OUT1, TX_OUT2, TX_OUT3, TX_OUT4, TX_OUT5, TX_OUT6, TX_OUT7, TX_OUT8, TX_OUT9, TX_OUT10, TX_OUT11, TX_OUT12, TX_OUT13, TX_OUT14, TX_OUT15, TX_OUT16, TX_OUT17, TX_OUT18, TX_OUT19, TX_OUT20, TX_OUT21, TX_OUT22, TX_OUT23, TX_OUT24, TX_OUT25, TX_OUT26, TX_OUT27, TX_OUT28, TX_OUT29, TX_OUT30, TX_OUT31, TX_OUT32
net class U28B_TX_OUT_33_64: TX_OUT33, TX_OUT34, TX_OUT35, TX_OUT36, TX_OUT37, TX_OUT38, TX_OUT39, TX_OUT40, TX_OUT41, TX_OUT42, TX_OUT43, TX_OUT44, TX_OUT45, TX_OUT46, TX_OUT47, TX_OUT48, TX_OUT49, TX_OUT50, TX_OUT51, TX_OUT52, TX_OUT53, TX_OUT54, TX_OUT55, TX_OUT56, TX_OUT57, TX_OUT58, TX_OUT59, TX_OUT60, TX_OUT61, TX_OUT62, TX_OUT63, TX_OUT64

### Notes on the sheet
- DNP J7, J8, J13, J14
- These test connectors should be in line with signal path
- Use GPIO to control LEs
- 0E use for debugging daisy-chain mode and parallel mode

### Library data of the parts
C307 C311 C379 C383 = CMP-0079630-1: CAP, CERM, 1 µF, 16 V,+/- 10%, X7R, AEC-Q200 Grade 1, 0805; Manufacturer: Kemet; TaMin_C: -55°C; Polarized: N; SizeAreaWB_mm2: 6.75; U/M: EA; Value: 1uF; TaMax_C: 125°C; SizeZ_mm: 1.45; SizeX_mm: 2; SizeY_mm: 1.25; Cap_Case: 0805; SizeArea_mm2: 2.5; AEC Qualified: Y; AEC Grade: 1; AEC Category: Q200
C308-C310 C312-C314 C380-C382 C384-C386 = CMP-0009637-3: as C281-C288 on sheet 21_TX7516_PartBPinout
J7 J8 J13 J14 J19 J22 = CMP-0054794-2: Header, 2.54 mm, 2x1, Gold, TH; Manufacturer: Wurth Elektronik; Pitch_mm: 2.54; Gender: Male; Cert_UL: Y; Shrouded: N; Row_Count: 1; Green_Lifecycle: Active; Green_REACh: Passed
R163 R294 = CMP-0078663-1: RES, 2.00 k, 1%, 0.1 W, AEC-Q200 Grade 0, 0603; Manufacturer: Panasonic; Power_W: 100mW; TempCo: 100 ppm/C; Value_Code: 2k00; Value: 2.00k; EIA_Code: E96; Res_ohm: 2k; SizeX_mm: 1.6; SizeY_mm: 0.8; SizeZ_mm: 1; Value2: 0.1W; SizeArea_mm2: 1.28; AEC Qualified: Y; AEC Grade: 0; AEC Category: Q200
R164 R165 R295 R296 = CMP-0022725-3: RES, 0, 1%, 0.1 W, AEC-Q200 Grade 1, 0603; Manufacturer: Panasonic; Power_W: 100mW; TempCo: 200 ppm/C; Value_Code: R100; Value: 0.1; EIA_Code: E96; SizeX_mm: 1.6; SizeY_mm: 0.8; SizeZ_mm: 1; Value2: 0.1W; SizeArea_mm2: 1.28; AEC Qualified: Y; AEC Category: Q200; SizeAreaWB_mm2: 4.68
R486 R488 R492 R509 R511 = CMP-0025874-4: RES, 0, 5%, 0.1 W, AEC-Q200 Grade 0, 0603; Manufacturer: Panasonic; Power_W: 100mW; TempCo: 600 ppm/C; Value_Code: 0000; Value: 0; EIA_Code: E24; SizeX_mm: 1.6; SizeY_mm: 0.8; SizeZ_mm: 1; Value2: 0.1W; SizeArea_mm2: 1.28; AEC Qualified: Y; VDC_V: 50V; AEC Category: Q200; SizeAreaWB_mm2: 4.68
TP37 TP40 = CMP-0003825-1: 1mm Test Point, SMT; Manufacturer: Any
U28 U29 = CMP-0094338-1: 5V Supply, 220V High Voltage 1:1, 32-Channel Switch with Latch-Up Immunity; Manufacturer: Texas Instruments; SizeZ_mm: 1.2mm; TaMin_C: -40°C; PositionCount: 32; On State Resistance: 8Ω; Min Supply Voltage: 4.5V; AEC Qualified: No; Nominal Supply Current: 2.8mA; Interface: SPI; Max Supply Voltage: 5.5V; TJmax_C: +150°C; Standoff Height: 0.19mm; TaMax_C: +85°C

## Sheet 23_TMUX9832(65-128)_Pinout.SchDoc
size 431 x 279 mm; Date: Not shown in title block; ApprovedBy: Not shown in title block; CheckedBy: Not shown in title block; Author: Not shown in title block; CompanyName: Not shown in title block; Engineer: Not shown in title block; Organization: Not shown in title block; Address1: Not shown in title block; Address2: Not shown in title block; Address3: Not shown in title block; Address4: Not shown in title block; DocumentNumber: 15; Revision: Use project parameter SCH_Rev; SheetNumber: 15; SheetTotal: 18; PageSetup: Record=PageOptions¦CenterHorizontal=True¦CenterVertical=True¦PrintScale=1.00¦XCorrection=1.00¦YCorrection=1.00¦PrintKind=0¦BorderSize=5000000¦LeftOffset=0¦BottomOffset=0¦Orientation=2¦PaperLength=1000¦PaperWidth=1000¦Scale=100¦PaperSource=15¦PrintQuality=600¦MediaType=1¦DitherType=10¦PaperKind=Letter¦PrintScaleMode=1
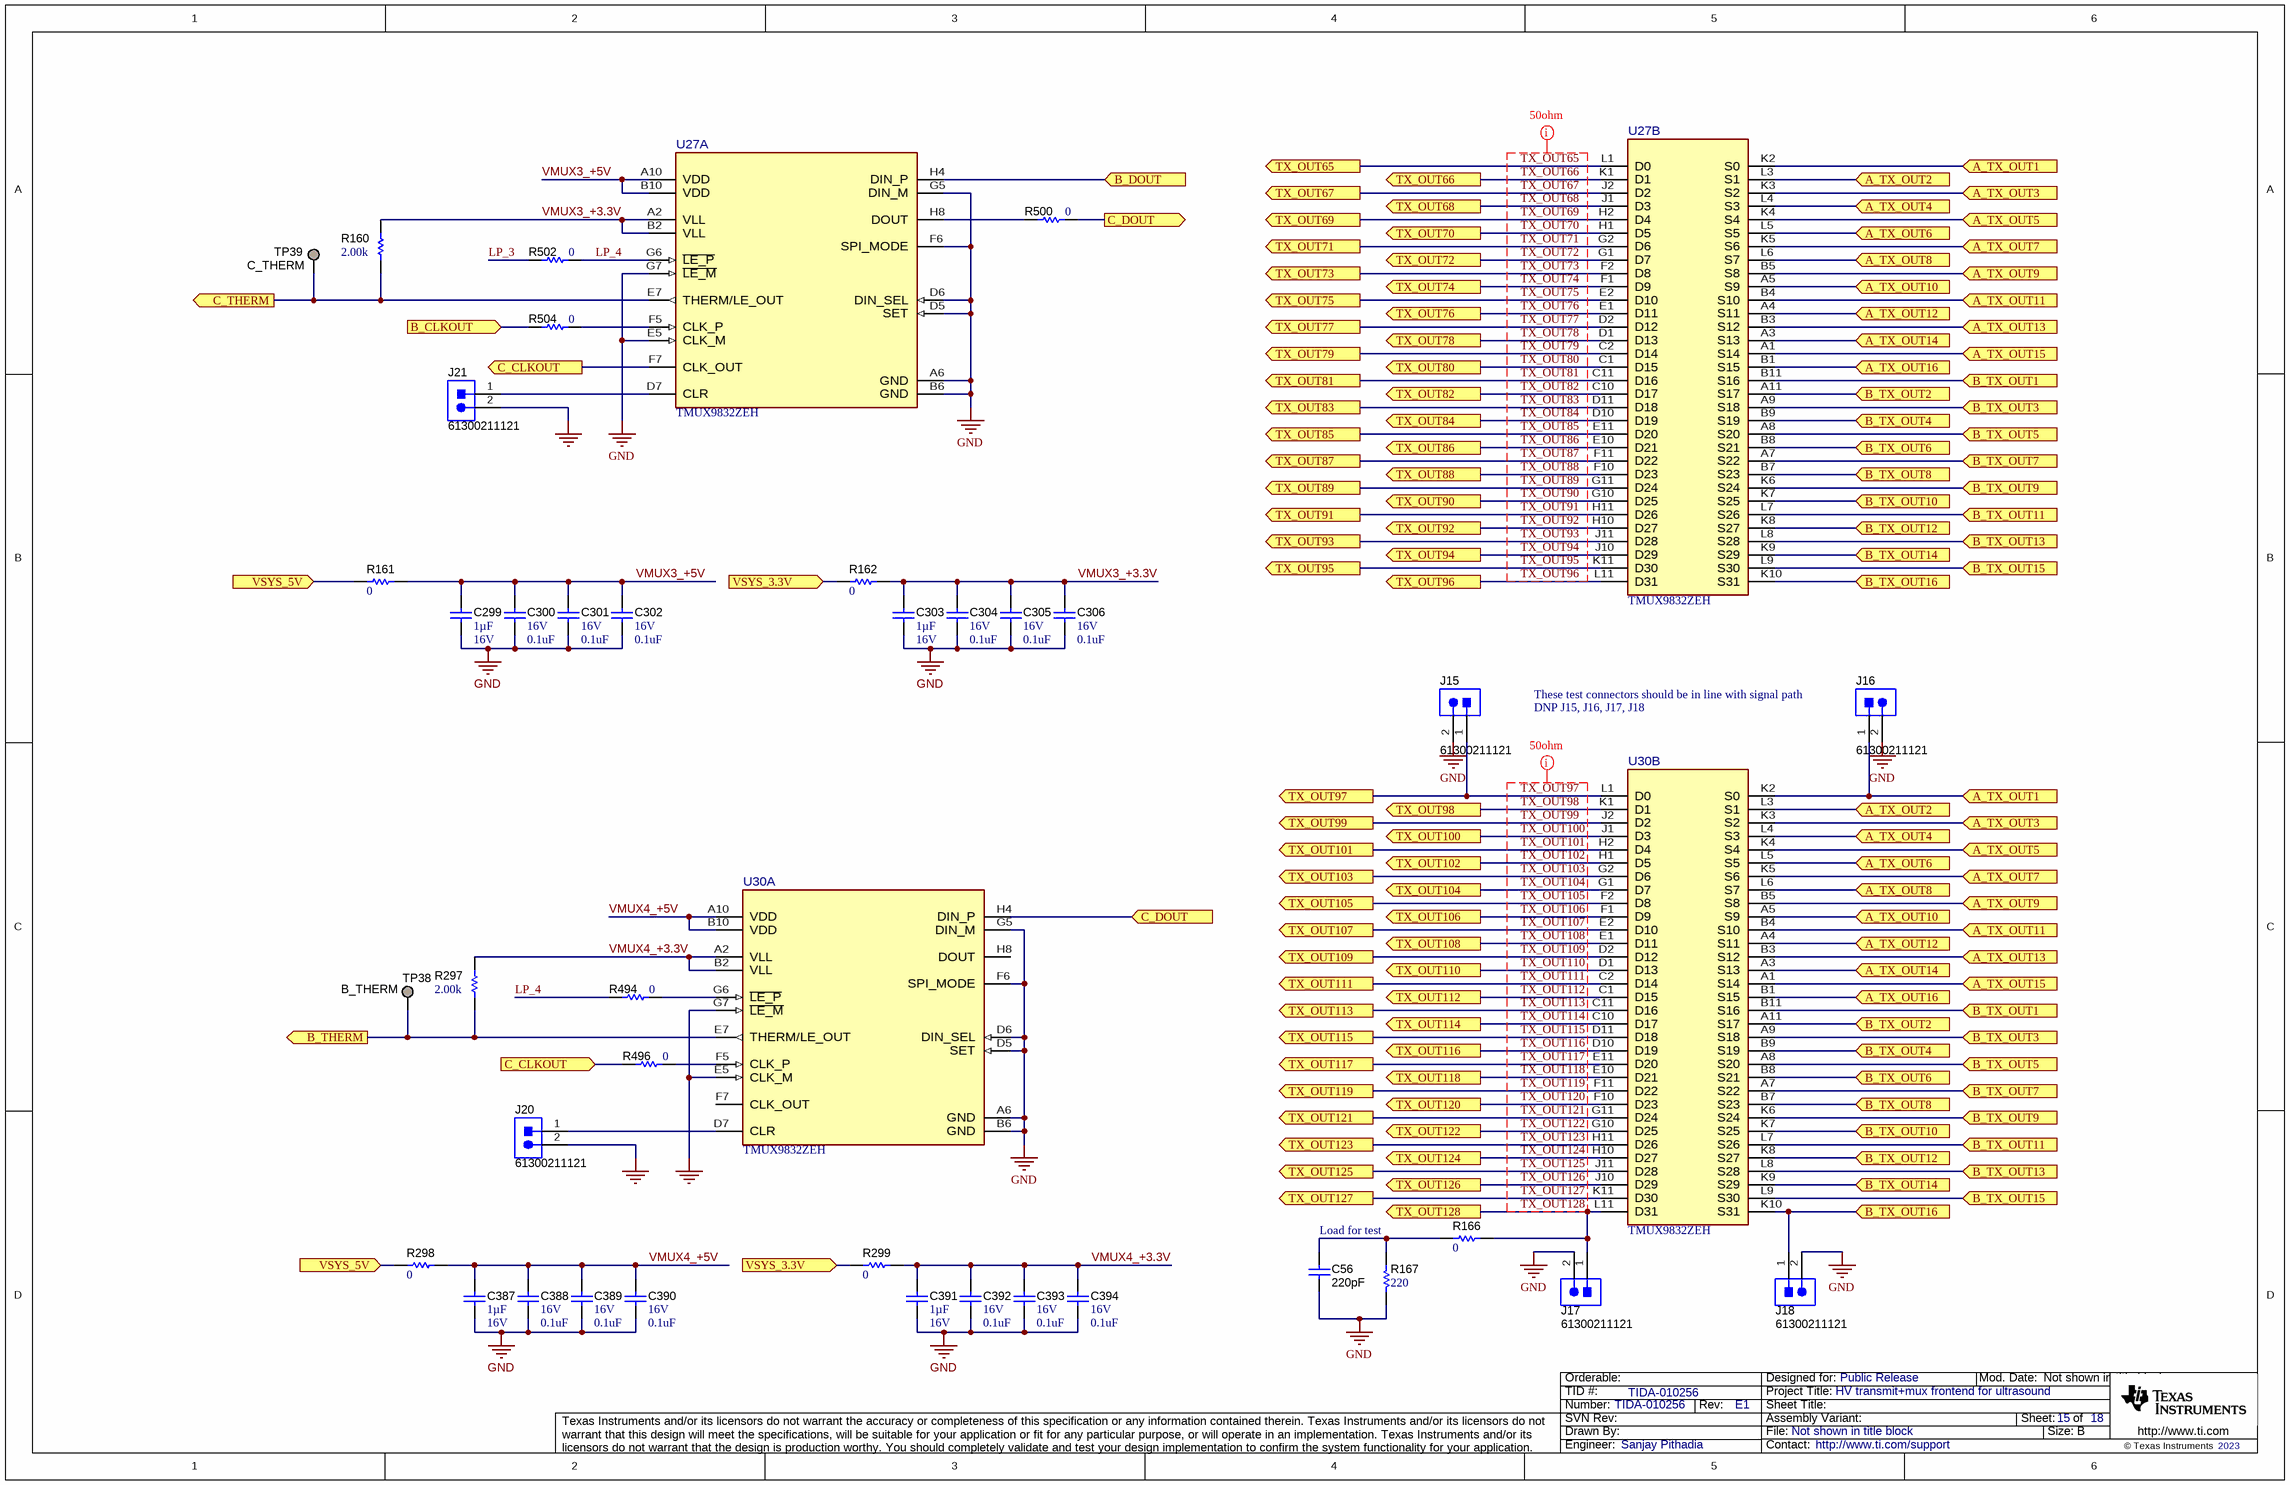
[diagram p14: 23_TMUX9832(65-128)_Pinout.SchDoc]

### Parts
C56  ValueDisplayed: 220pF  [0603]  (hidden comment: Capacitor)
C299  Cap_F: 1µF  VDC_V: 16V  [0805_HV]  (hidden comment: C0805C105K4RACAUTO)
C300  VDC_V: 16V  ValueDisplayed: 0.1uF  [0201_033]  (hidden comment: C0603X6S1C104K030BC)
C301  VDC_V: 16V  ValueDisplayed: 0.1uF  [0201_033]  (hidden comment: C0603X6S1C104K030BC)
C302  VDC_V: 16V  ValueDisplayed: 0.1uF  [0201_033]  (hidden comment: C0603X6S1C104K030BC)
C303  Cap_F: 1µF  VDC_V: 16V  [0805_HV]  (hidden comment: C0805C105K4RACAUTO)
C304  VDC_V: 16V  ValueDisplayed: 0.1uF  [0201_033]  (hidden comment: C0603X6S1C104K030BC)
C305  VDC_V: 16V  ValueDisplayed: 0.1uF  [0201_033]  (hidden comment: C0603X6S1C104K030BC)
C306  VDC_V: 16V  ValueDisplayed: 0.1uF  [0201_033]  (hidden comment: C0603X6S1C104K030BC)
C387  Cap_F: 1µF  VDC_V: 16V  [0805_HV]  (hidden comment: C0805C105K4RACAUTO)
C388  VDC_V: 16V  ValueDisplayed: 0.1uF  [0201_033]  (hidden comment: C0603X6S1C104K030BC)
C389  VDC_V: 16V  ValueDisplayed: 0.1uF  [0201_033]  (hidden comment: C0603X6S1C104K030BC)
C390  VDC_V: 16V  ValueDisplayed: 0.1uF  [0201_033]  (hidden comment: C0603X6S1C104K030BC)
C391  Cap_F: 1µF  VDC_V: 16V  [0805_HV]  (hidden comment: C0805C105K4RACAUTO)
C392  VDC_V: 16V  ValueDisplayed: 0.1uF  [0201_033]  (hidden comment: C0603X6S1C104K030BC)
C393  VDC_V: 16V  ValueDisplayed: 0.1uF  [0201_033]  (hidden comment: C0603X6S1C104K030BC)
C394  VDC_V: 16V  ValueDisplayed: 0.1uF  [0201_033]  (hidden comment: C0603X6S1C104K030BC)
J15  61300211121  [WURTH_61300211121]
J16  61300211121  [WURTH_61300211121]
J17  61300211121  [WURTH_61300211121]
J18  61300211121  [WURTH_61300211121]
J20  61300211121  [WURTH_61300211121]
J21  61300211121  [WURTH_61300211121]
R160  ValueDisplayed: 2.00k  [0603]  (hidden comment: ERJ3EKF2001V)
R161  ValueDisplayed: 0  [0603]  (hidden comment: ERJ-L03KF10CV)
R162  ValueDisplayed: 0  [0603]  (hidden comment: ERJ-L03KF10CV)
R166  ValueDisplayed: 0  [0603]  (hidden comment: ERJ-3GEY0R00V)
R167  ValueDisplayed: 220  [2512]  (hidden comment: CRCW2512220RFKEG)
R297  ValueDisplayed: 2.00k  [0603]  (hidden comment: ERJ3EKF2001V)
R298  ValueDisplayed: 0  [0603]  (hidden comment: ERJ-L03KF10CV)
R299  ValueDisplayed: 0  [0603]  (hidden comment: ERJ-L03KF10CV)
R494  ValueDisplayed: 0  [0603]  (hidden comment: ERJ-3GEY0R00V)
R496  ValueDisplayed: 0  [0603]  (hidden comment: ERJ-3GEY0R00V)
R500  ValueDisplayed: 0  [0603]  (hidden comment: ERJ-3GEY0R00V)
R502  ValueDisplayed: 0  [0603]  (hidden comment: ERJ-3GEY0R00V)
R504  ValueDisplayed: 0  [0603]  (hidden comment: ERJ-3GEY0R00V)
TP38  B_THERM  [TP_SM_1MM]  (no BOM)
TP39  C_THERM  [TP_SM_1MM]  (no BOM)
U27  TMUX9832ZEH  [ZEH0083A-MFG]  (parts A,B of 2)
U30  TMUX9832ZEH  [ZEH0083A-MFG]  (parts A,B of 2)

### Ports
A_TX_OUT1 (in), A_TX_OUT2 (in), A_TX_OUT3 (in), A_TX_OUT4 (in), A_TX_OUT5 (in), A_TX_OUT6 (in), A_TX_OUT7 (in), A_TX_OUT8 (in), A_TX_OUT9 (in), A_TX_OUT10 (in), A_TX_OUT11 (in), A_TX_OUT12 (in), A_TX_OUT13 (in), A_TX_OUT14 (in), A_TX_OUT15 (in), A_TX_OUT16 (in), B_CLKOUT (in), B_DOUT (in), B_THERM (out), B_TX_OUT1 (in), B_TX_OUT2 (in), B_TX_OUT3 (in), B_TX_OUT4 (in), B_TX_OUT5 (in), B_TX_OUT6 (in), B_TX_OUT7 (in), B_TX_OUT8 (in), B_TX_OUT9 (in), B_TX_OUT10 (in), B_TX_OUT11 (in), B_TX_OUT12 (in), B_TX_OUT13 (in), B_TX_OUT14 (in), B_TX_OUT15 (in), B_TX_OUT16 (in), C_CLKOUT (in), C_CLKOUT (out), C_DOUT (in), C_DOUT (out), C_THERM (out), TX_OUT65 (out), TX_OUT66 (out), TX_OUT67 (out), TX_OUT68 (out), TX_OUT69 (out), TX_OUT70 (out), TX_OUT71 (out), TX_OUT72 (out), TX_OUT73 (out), TX_OUT74 (out), TX_OUT75 (out), TX_OUT76 (out), TX_OUT77 (out), TX_OUT78 (out), TX_OUT79 (out), TX_OUT80 (out), TX_OUT81 (out), TX_OUT82 (out), TX_OUT83 (out), TX_OUT84 (out), TX_OUT85 (out), TX_OUT86 (out), TX_OUT87 (out), TX_OUT88 (out), TX_OUT89 (out), TX_OUT90 (out), TX_OUT91 (out), TX_OUT92 (out), TX_OUT93 (out), TX_OUT94 (out), TX_OUT95 (out), TX_OUT96 (out), TX_OUT97 (out), TX_OUT98 (out), TX_OUT99 (out), TX_OUT100 (out), TX_OUT101 (out), TX_OUT102 (out), TX_OUT103 (out), TX_OUT104 (out), TX_OUT105 (out), TX_OUT106 (out), TX_OUT107 (out), TX_OUT108 (out), TX_OUT109 (out), TX_OUT110 (out), TX_OUT111 (out), TX_OUT112 (out), TX_OUT113 (out), TX_OUT114 (out), TX_OUT115 (out), TX_OUT116 (out), TX_OUT117 (out), TX_OUT118 (out), TX_OUT119 (out), TX_OUT120 (out), TX_OUT121 (out), TX_OUT122 (out), TX_OUT123 (out), TX_OUT124 (out), TX_OUT125 (out), TX_OUT126 (out), TX_OUT127 (out), TX_OUT128 (out), VSYS_3.3V (in), VSYS_5V (in)

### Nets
GND: C56.1 C299.2 C300.2 C301.2 C302.2 C303.2 C304.2 C305.2 C306.2 C387.2 C388.2 C389.2 C390.2 C391.2 C392.2 C393.2 C394.2 J15.2 J16.2 J17.2 J18.2 J20.2 J21.2 R167.1 U27.A6(GND) U27.B6(GND) U27.D5(SET) U27.D6(DIN_SEL) U27.E5(CLK_M) U27.F6(SPI_MODE) U27.G5(DIN_M) U27.G7(~{LE_M}) U30.A6(GND) U30.B6(GND) U30.D5(SET) U30.D6(DIN_SEL) U30.E5(CLK_M) U30.F6(SPI_MODE) U30.G5(DIN_M) U30.G7(~{LE_M})
A_TX_OUT1: J16.1 U27.K2(S0) U30.K2(S0) ; port A_TX_OUT1
A_TX_OUT2: U27.L3(S1) U30.L3(S1) ; port A_TX_OUT2
A_TX_OUT3: U27.K3(S2) U30.K3(S2) ; port A_TX_OUT3
A_TX_OUT4: U27.L4(S3) U30.L4(S3) ; port A_TX_OUT4
A_TX_OUT5: U27.K4(S4) U30.K4(S4) ; port A_TX_OUT5
A_TX_OUT6: U27.L5(S5) U30.L5(S5) ; port A_TX_OUT6
A_TX_OUT7: U27.K5(S6) U30.K5(S6) ; port A_TX_OUT7
A_TX_OUT8: U27.L6(S7) U30.L6(S7) ; port A_TX_OUT8
A_TX_OUT9: U27.B5(S8) U30.B5(S8) ; port A_TX_OUT9
A_TX_OUT10: U27.A5(S9) U30.A5(S9) ; port A_TX_OUT10
A_TX_OUT11: U27.B4(S10) U30.B4(S10) ; port A_TX_OUT11
A_TX_OUT12: U27.A4(S11) U30.A4(S11) ; port A_TX_OUT12
A_TX_OUT13: U27.B3(S12) U30.B3(S12) ; port A_TX_OUT13
A_TX_OUT14: U27.A3(S13) U30.A3(S13) ; port A_TX_OUT14
A_TX_OUT15: U27.A1(S14) U30.A1(S14) ; port A_TX_OUT15
A_TX_OUT16: U27.B1(S15) U30.B1(S15) ; port A_TX_OUT16
B_TX_OUT1: U27.B11(S16) U30.B11(S16) ; port B_TX_OUT1
B_TX_OUT2: U27.A11(S17) U30.A11(S17) ; port B_TX_OUT2
B_TX_OUT3: U27.A9(S18) U30.A9(S18) ; port B_TX_OUT3
B_TX_OUT4: U27.B9(S19) U30.B9(S19) ; port B_TX_OUT4
B_TX_OUT5: U27.A8(S20) U30.A8(S20) ; port B_TX_OUT5
B_TX_OUT6: U27.B8(S21) U30.B8(S21) ; port B_TX_OUT6
B_TX_OUT7: U27.A7(S22) U30.A7(S22) ; port B_TX_OUT7
B_TX_OUT8: U27.B7(S23) U30.B7(S23) ; port B_TX_OUT8
B_TX_OUT9: U27.K6(S24) U30.K6(S24) ; port B_TX_OUT9
B_TX_OUT10: U27.K7(S25) U30.K7(S25) ; port B_TX_OUT10
B_TX_OUT11: U27.L7(S26) U30.L7(S26) ; port B_TX_OUT11
B_TX_OUT12: U27.K8(S27) U30.K8(S27) ; port B_TX_OUT12
B_TX_OUT13: U27.L8(S28) U30.L8(S28) ; port B_TX_OUT13
B_TX_OUT14: U27.K9(S29) U30.K9(S29) ; port B_TX_OUT14
B_TX_OUT15: U27.L9(S30) U30.L9(S30) ; port B_TX_OUT15
B_TX_OUT16: J18.1 U27.K10(S31) U30.K10(S31) ; port B_TX_OUT16
LP_3: R502.1
LP_4: R494.1 R502.2 U27.G6(~{LE_P})
TX_OUT65: U27.L1(D0) ; port TX_OUT65
TX_OUT66: U27.K1(D1) ; port TX_OUT66
TX_OUT67: U27.J2(D2) ; port TX_OUT67
TX_OUT68: U27.J1(D3) ; port TX_OUT68
TX_OUT69: U27.H2(D4) ; port TX_OUT69
TX_OUT70: U27.H1(D5) ; port TX_OUT70
TX_OUT71: U27.G2(D6) ; port TX_OUT71
TX_OUT72: U27.G1(D7) ; port TX_OUT72
TX_OUT73: U27.F2(D8) ; port TX_OUT73
TX_OUT74: U27.F1(D9) ; port TX_OUT74
TX_OUT75: U27.E2(D10) ; port TX_OUT75
TX_OUT76: U27.E1(D11) ; port TX_OUT76
TX_OUT77: U27.D2(D12) ; port TX_OUT77
TX_OUT78: U27.D1(D13) ; port TX_OUT78
TX_OUT79: U27.C2(D14) ; port TX_OUT79
TX_OUT80: U27.C1(D15) ; port TX_OUT80
TX_OUT81: U27.C11(D16) ; port TX_OUT81
TX_OUT82: U27.C10(D17) ; port TX_OUT82
TX_OUT83: U27.D11(D18) ; port TX_OUT83
TX_OUT84: U27.D10(D19) ; port TX_OUT84
TX_OUT85: U27.E11(D20) ; port TX_OUT85
TX_OUT86: U27.E10(D21) ; port TX_OUT86
TX_OUT87: U27.F11(D22) ; port TX_OUT87
TX_OUT88: U27.F10(D23) ; port TX_OUT88
TX_OUT89: U27.G11(D24) ; port TX_OUT89
TX_OUT90: U27.G10(D25) ; port TX_OUT90
TX_OUT91: U27.H11(D26) ; port TX_OUT91
TX_OUT92: U27.H10(D27) ; port TX_OUT92
TX_OUT93: U27.J11(D28) ; port TX_OUT93
TX_OUT94: U27.J10(D29) ; port TX_OUT94
TX_OUT95: U27.K11(D30) ; port TX_OUT95
TX_OUT96: U27.L11(D31) ; port TX_OUT96
TX_OUT97: J15.1 U30.L1(D0) ; port TX_OUT97
TX_OUT98: U30.K1(D1) ; port TX_OUT98
TX_OUT99: U30.J2(D2) ; port TX_OUT99
TX_OUT100: U30.J1(D3) ; port TX_OUT100
TX_OUT101: U30.H2(D4) ; port TX_OUT101
TX_OUT102: U30.H1(D5) ; port TX_OUT102
TX_OUT103: U30.G2(D6) ; port TX_OUT103
TX_OUT104: U30.G1(D7) ; port TX_OUT104
TX_OUT105: U30.F2(D8) ; port TX_OUT105
TX_OUT106: U30.F1(D9) ; port TX_OUT106
TX_OUT107: U30.E2(D10) ; port TX_OUT107
TX_OUT108: U30.E1(D11) ; port TX_OUT108
TX_OUT109: U30.D2(D12) ; port TX_OUT109
TX_OUT110: U30.D1(D13) ; port TX_OUT110
TX_OUT111: U30.C2(D14) ; port TX_OUT111
TX_OUT112: U30.C1(D15) ; port TX_OUT112
TX_OUT113: U30.C11(D16) ; port TX_OUT113
TX_OUT114: U30.C10(D17) ; port TX_OUT114
TX_OUT115: U30.D11(D18) ; port TX_OUT115
TX_OUT116: U30.D10(D19) ; port TX_OUT116
TX_OUT117: U30.E11(D20) ; port TX_OUT117
TX_OUT118: U30.E10(D21) ; port TX_OUT118
TX_OUT119: U30.F11(D22) ; port TX_OUT119
TX_OUT120: U30.F10(D23) ; port TX_OUT120
TX_OUT121: U30.G11(D24) ; port TX_OUT121
TX_OUT122: U30.G10(D25) ; port TX_OUT122
TX_OUT123: U30.H11(D26) ; port TX_OUT123
TX_OUT124: U30.H10(D27) ; port TX_OUT124
TX_OUT125: U30.J11(D28) ; port TX_OUT125
TX_OUT126: U30.J10(D29) ; port TX_OUT126
TX_OUT127: U30.K11(D30) ; port TX_OUT127
TX_OUT128: J17.1 R166.2 U30.L11(D31) ; port TX_OUT128
VMUX3_+3.3V: C303.1 C304.1 C305.1 C306.1 R160.2 R162.2 U27.A2(VLL) U27.B2(VLL)
VMUX3_+5V: C299.1 C300.1 C301.1 C302.1 R161.2 U27.A10(VDD) U27.B10(VDD)
VMUX4_+3.3V: C391.1 C392.1 C393.1 C394.1 R297.2 R299.2 U30.A2(VLL) U30.B2(VLL)
VMUX4_+5V: C387.1 C388.1 C389.1 C390.1 R298.2 U30.A10(VDD) U30.B10(VDD)
VSYS_3.3V: R162.1 R299.1 ; port VSYS_3.3V
VSYS_5V: R161.1 R298.1 ; port VSYS_5V
NetC56_2: C56.2 R166.1 R167.2
NetJ20_1: J20.1 U30.D7(CLR)
NetJ21_1: J21.1 U27.D7(CLR)
NetR160_1: R160.1 TP39.1 U27.E7(THERM/LE_OUT) ; port C_THERM
NetR297_1: R297.1 TP38.1 U30.E7(THERM/LE_OUT) ; port B_THERM
NetR492_2: U27.H4(DIN_P) ; port B_DOUT
NetR494_2: R494.2 U30.G6(~{LE_P})
NetR496_1: R496.1 U27.F7(CLK_OUT) ; port C_CLKOUT
NetR496_2: R496.2 U30.F5(CLK_P)
NetR500_1: R500.1 U27.H8(DOUT)
NetR500_2: R500.2 U30.H4(DIN_P) ; port C_DOUT
NetR504_1: R504.1 ; port B_CLKOUT
NetR504_2: R504.2 U27.F5(CLK_P)

Not connected (* = marked no-connect by the designer): U30 F7(CLK_OUT) H8(DOUT)

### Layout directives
net class U27B_TX_OUT_65_96: TX_OUT65, TX_OUT66, TX_OUT67, TX_OUT68, TX_OUT69, TX_OUT70, TX_OUT71, TX_OUT72, TX_OUT73, TX_OUT74, TX_OUT75, TX_OUT76, TX_OUT77, TX_OUT78, TX_OUT79, TX_OUT80, TX_OUT81, TX_OUT82, TX_OUT83, TX_OUT84, TX_OUT85, TX_OUT86, TX_OUT87, TX_OUT88, TX_OUT89, TX_OUT90, TX_OUT91, TX_OUT92, TX_OUT93, TX_OUT94, TX_OUT95, TX_OUT96
net class U30B_TX_OUT_97_128: TX_OUT97, TX_OUT98, TX_OUT99, TX_OUT100, TX_OUT101, TX_OUT102, TX_OUT103, TX_OUT104, TX_OUT105, TX_OUT106, TX_OUT107, TX_OUT108, TX_OUT109, TX_OUT110, TX_OUT111, TX_OUT112, TX_OUT113, TX_OUT114, TX_OUT115, TX_OUT116, TX_OUT117, TX_OUT118, TX_OUT119, TX_OUT120, TX_OUT121, TX_OUT122, TX_OUT123, TX_OUT124, TX_OUT125, TX_OUT126, TX_OUT127, TX_OUT128

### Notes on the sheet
- (near J16) These test connectors should be in line with signal path
- DNP J15, J16, J17, J18
- Load for test

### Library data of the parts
C56 = CMP-0006996-4: CAP, CERM, 220 pF, 250 V, +/- 5%, C0G/NP0, 0603; PartNumber: C1608C0G2E221J080AA; Manufacturer: TDK; Polarized: N; Value: 220pF; U/M: EA; Value1: Unknown; VDC_V: 250V; TaMin_C: -55°C; TaMax_C: 125°C; SizeArea_mm2: 1.28; SizeAreaWB_mm2: 4.68; SizeX_mm: 1.6; SizeY_mm: 0.8; SizeZ_mm: 1; AEC Category: Q200
C299 C303 C387 C391 = CMP-0079630-1: as C307 on sheet 22_TMUX9832(0-64)_Pinout
C300-C302 C304-C306 C388-C390 C392-C394 = CMP-0009637-3: as C281-C288 on sheet 21_TX7516_PartBPinout
J15-J18 J20 J21 = CMP-0054794-2: as J7 on sheet 22_TMUX9832(0-64)_Pinout
R160 R297 = CMP-0078663-1: as R163 on sheet 22_TMUX9832(0-64)_Pinout
R161 R162 R298 R299 = CMP-0022725-3: as R164 on sheet 22_TMUX9832(0-64)_Pinout
R166 R494 R496 R500 R502 R504 = CMP-0025874-4: as R486 on sheet 22_TMUX9832(0-64)_Pinout
R167 = CMP-0015538-3: RES, 220, 1%, 1 W, AEC-Q200 Grade 0, 2512; Manufacturer: Vishay-Dale; Power_W: 1W; TempCo: 100 ppm/C; Value_Code: 220R; Value: 220; SizeX_mm: 6.3; SizeY_mm: 3.2; SizeZ_mm: 0.71; SizeArea_mm2: 20.16; AEC Qualified: Y; VDC_V: 500V; AEC Grade: 0; AEC Category: Q200
TP38 TP39 = CMP-0003825-1: 1mm Test Point, SMT; Manufacturer: Any
U27 U30 = CMP-0094338-1: as U28 on sheet 22_TMUX9832(0-64)_Pinout

## Sheet 24_TX_Connector(no load resitor).SchDoc
size 431 x 279 mm; Date: Not shown in title block; ApprovedBy: Not shown in title block; CheckedBy: Not shown in title block; Author: Not shown in title block; CompanyName: Not shown in title block; Engineer: Not shown in title block; Organization: Not shown in title block; Address1: Not shown in title block; Address2: Not shown in title block; Address3: Not shown in title block; Address4: Not shown in title block; DocumentNumber: 16; Revision: Use project parameter SCH_Rev; SheetNumber: 16; SheetTotal: 18; PageSetup: Record=PageOptions¦CenterHorizontal=True¦CenterVertical=True¦PrintScale=1.00¦XCorrection=1.00¦YCorrection=1.00¦PrintKind=0¦BorderSize=5000000¦LeftOffset=0¦BottomOffset=0¦Orientation=2¦PaperLength=1000¦PaperWidth=1000¦Scale=100¦PaperSource=15¦PrintQuality=600¦MediaType=1¦DitherType=10¦PaperKind=Letter¦PrintScaleMode=1
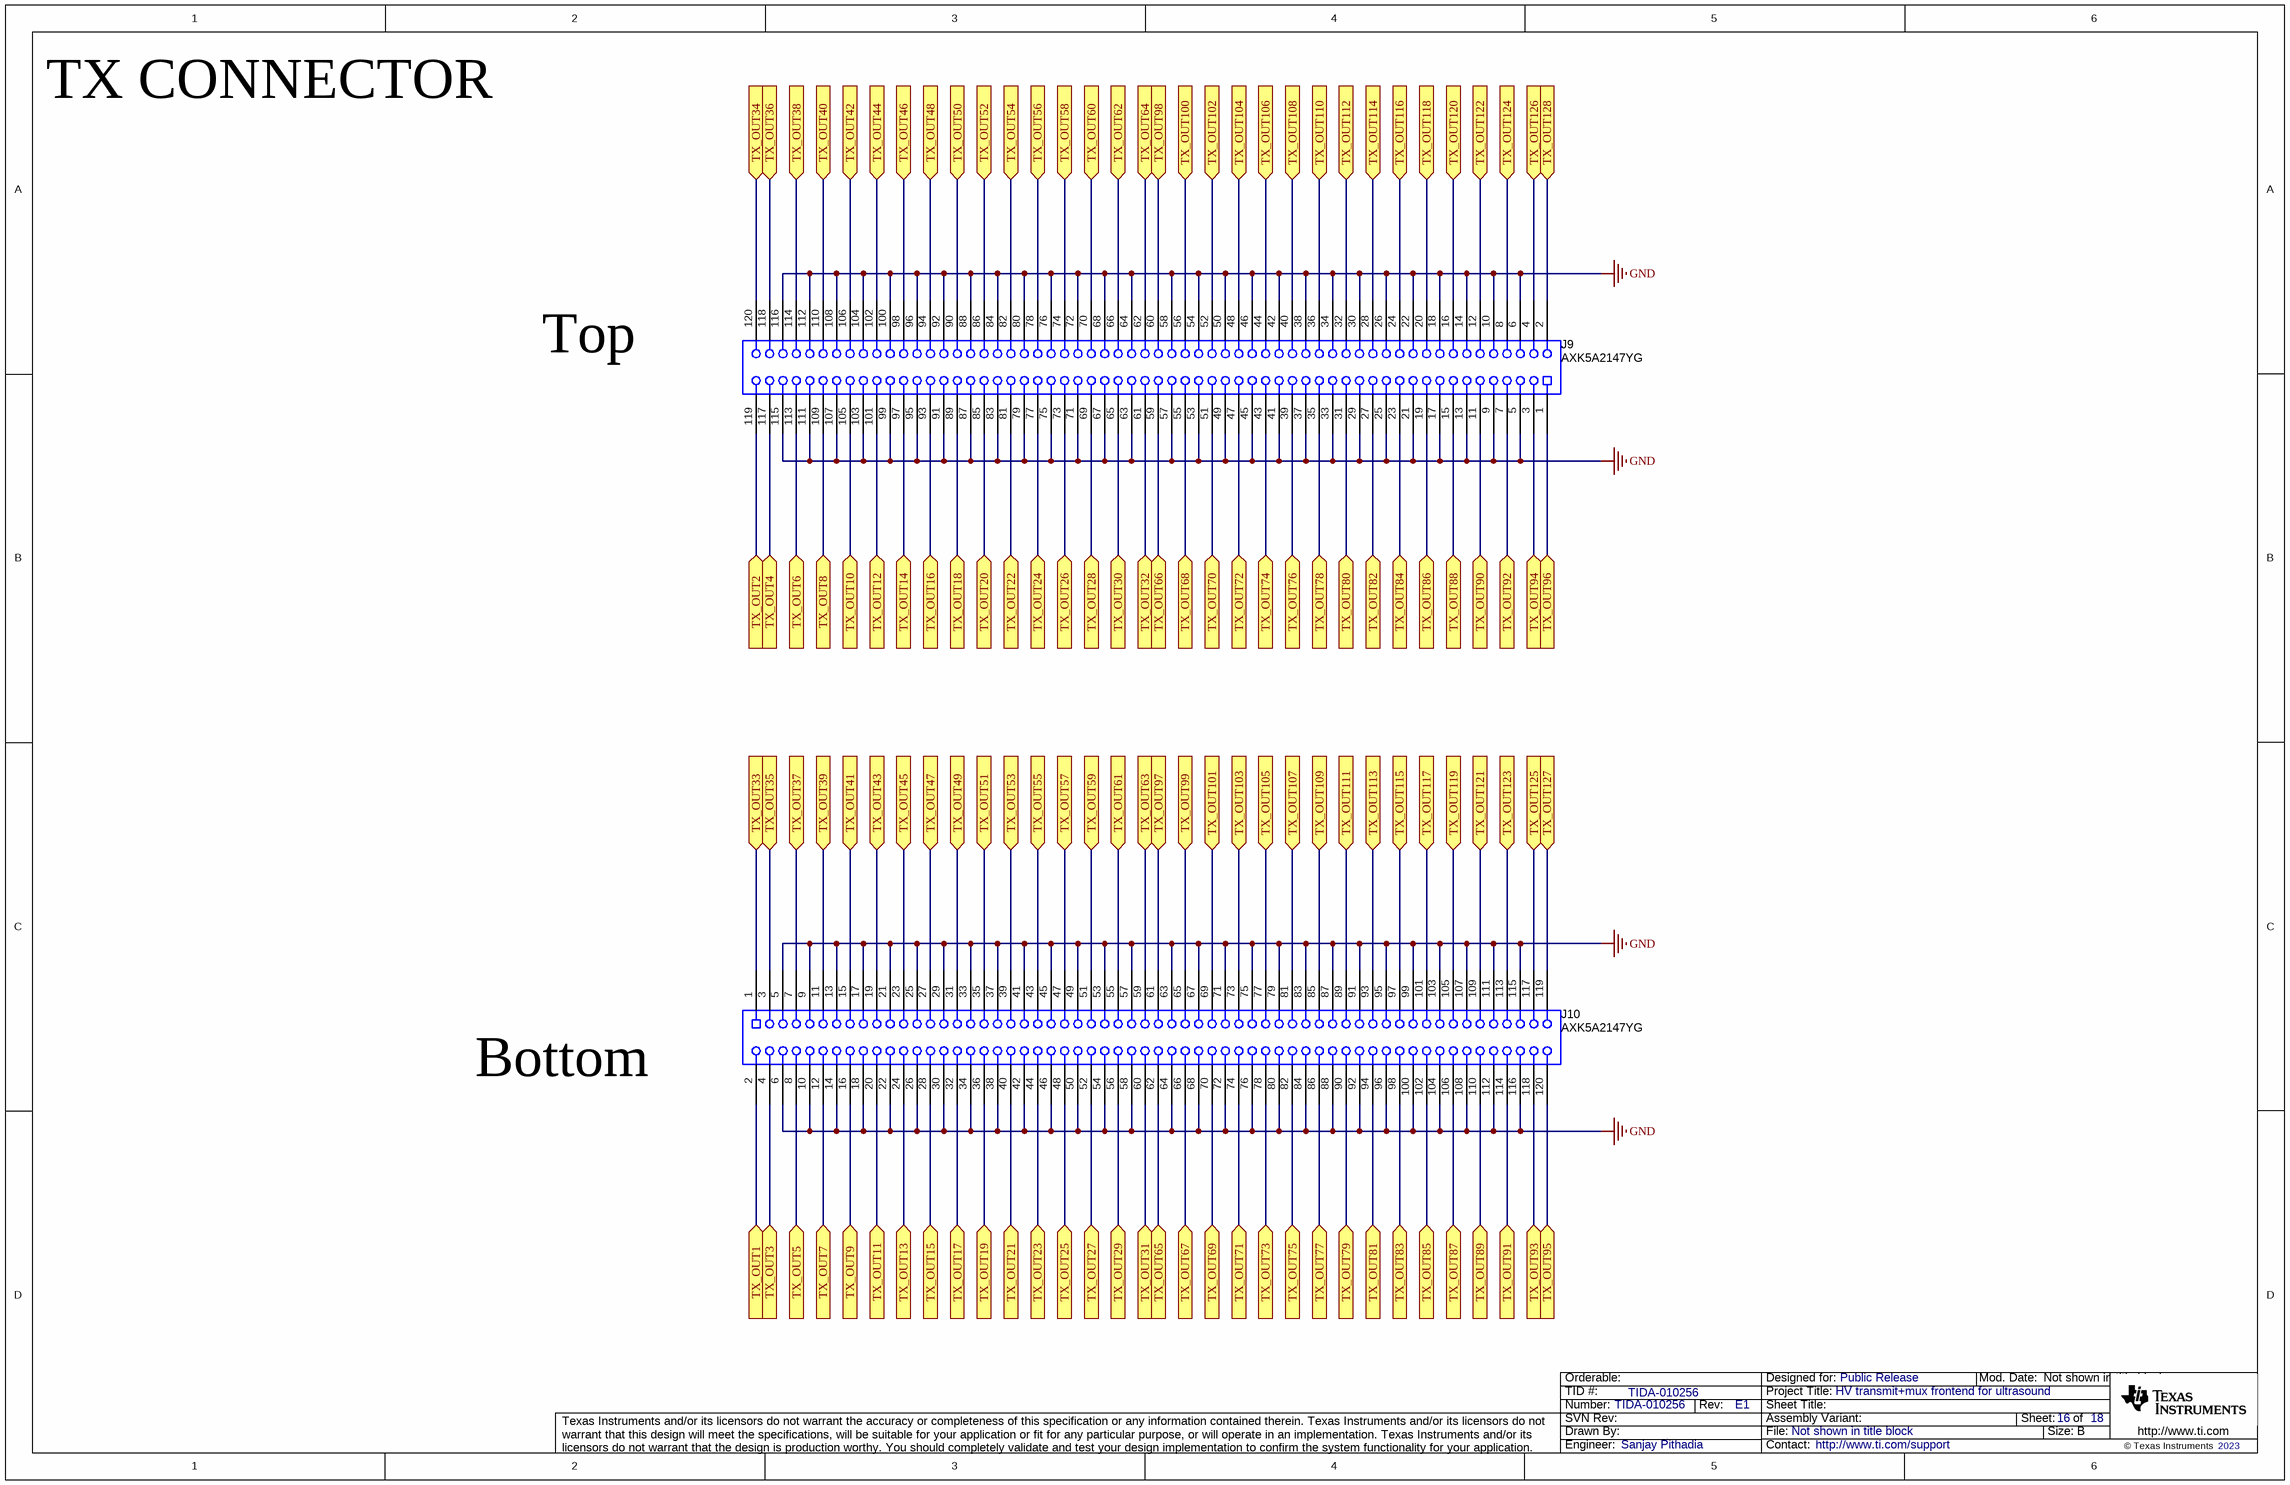
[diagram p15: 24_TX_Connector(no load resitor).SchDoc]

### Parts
J9  AXK5A2147YG  [Panasonic_AXK5A2147YG]
J10  AXK5A2147YG  [Panasonic_AXK5A2147YG]

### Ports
TX_OUT1 (in), TX_OUT2 (in), TX_OUT3 (in), TX_OUT4 (in), TX_OUT5 (in), TX_OUT6 (in), TX_OUT7 (in), TX_OUT8 (in), TX_OUT9 (in), TX_OUT10 (in), TX_OUT11 (in), TX_OUT12 (in), TX_OUT13 (in), TX_OUT14 (in), TX_OUT15 (in), TX_OUT16 (in), TX_OUT17 (in), TX_OUT18 (in), TX_OUT19 (in), TX_OUT20 (in), TX_OUT21 (in), TX_OUT22 (in), TX_OUT23 (in), TX_OUT24 (in), TX_OUT25 (in), TX_OUT26 (in), TX_OUT27 (in), TX_OUT28 (in), TX_OUT29 (in), TX_OUT30 (in), TX_OUT31 (in), TX_OUT32 (in), TX_OUT33 (in), TX_OUT34 (in), TX_OUT35 (in), TX_OUT36 (in), TX_OUT37 (in), TX_OUT38 (in), TX_OUT39 (in), TX_OUT40 (in), TX_OUT41 (in), TX_OUT42 (in), TX_OUT43 (in), TX_OUT44 (in), TX_OUT45 (in), TX_OUT46 (in), TX_OUT47 (in), TX_OUT48 (in), TX_OUT49 (in), TX_OUT50 (in), TX_OUT51 (in), TX_OUT52 (in), TX_OUT53 (in), TX_OUT54 (in), TX_OUT55 (in), TX_OUT56 (in), TX_OUT57 (in), TX_OUT58 (in), TX_OUT59 (in), TX_OUT60 (in), TX_OUT61 (in), TX_OUT62 (in), TX_OUT63 (in), TX_OUT64 (in), TX_OUT65 (in), TX_OUT66 (in), TX_OUT67 (in), TX_OUT68 (in), TX_OUT69 (in), TX_OUT70 (in), TX_OUT71 (in), TX_OUT72 (in), TX_OUT73 (in), TX_OUT74 (in), TX_OUT75 (in), TX_OUT76 (in), TX_OUT77 (in), TX_OUT78 (in), TX_OUT79 (in), TX_OUT80 (in), TX_OUT81 (in), TX_OUT82 (in), TX_OUT83 (in), TX_OUT84 (in), TX_OUT85 (in), TX_OUT86 (in), TX_OUT87 (in), TX_OUT88 (in), TX_OUT89 (in), TX_OUT90 (in), TX_OUT91 (in), TX_OUT92 (in), TX_OUT93 (in), TX_OUT94 (in), TX_OUT95 (in), TX_OUT96 (in), TX_OUT97 (in), TX_OUT98 (in), TX_OUT99 (in), TX_OUT100 (in), TX_OUT101 (in), TX_OUT102 (in), TX_OUT103 (in), TX_OUT104 (in), TX_OUT105 (in), TX_OUT106 (in), TX_OUT107 (in), TX_OUT108 (in), TX_OUT109 (in), TX_OUT110 (in), TX_OUT111 (in), TX_OUT112 (in), TX_OUT113 (in), TX_OUT114 (in), TX_OUT115 (in), TX_OUT116 (in), TX_OUT117 (in), TX_OUT118 (in), TX_OUT119 (in), TX_OUT120 (in), TX_OUT121 (in), TX_OUT122 (in), TX_OUT123 (in), TX_OUT124 (in), TX_OUT125 (in), TX_OUT126 (in), TX_OUT127 (in), TX_OUT128 (in)

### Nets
GND: J9.5 J9.6 J9.9 J9.10 J9.13 J9.14 J9.17 J9.18 J9.21 J9.22 J9.25 J9.26 J9.29 J9.30 J9.33 J9.34 J9.37 J9.38 J9.41 J9.42 J9.45 J9.46 J9.49 J9.50 J9.53 J9.54 J9.57 J9.58 J9.63 J9.64 J9.67 J9.68 J9.71 J9.72 J9.75 J9.76 J9.79 J9.80 J9.83 J9.84 J9.87 J9.88 J9.91 J9.92 J9.95 J9.96 J9.99 J9.100 J9.103 J9.104 J9.107 J9.108 J9.111 J9.112 J9.115 J9.116 J10.5 J10.6 J10.9 J10.10 J10.13 J10.14 J10.17 J10.18 J10.21 J10.22 J10.25 J10.26 J10.29 J10.30 J10.33 J10.34 J10.37 J10.38 J10.41 J10.42 J10.45 J10.46 J10.49 J10.50 J10.53 J10.54 J10.57 J10.58 J10.63 J10.64 J10.67 J10.68 J10.71 J10.72 J10.75 J10.76 J10.79 J10.80 J10.83 J10.84 J10.87 J10.88 J10.91 J10.92 J10.95 J10.96 J10.99 J10.100 J10.103 J10.104 J10.107 J10.108 J10.111 J10.112 J10.115 J10.116
TX_OUT1: J10.2 ; port TX_OUT1
TX_OUT2: J9.119 ; port TX_OUT2
TX_OUT3: J10.4 ; port TX_OUT3
TX_OUT4: J9.117 ; port TX_OUT4
TX_OUT5: J10.8 ; port TX_OUT5
TX_OUT6: J9.113 ; port TX_OUT6
TX_OUT7: J10.12 ; port TX_OUT7
TX_OUT8: J9.109 ; port TX_OUT8
TX_OUT9: J10.16 ; port TX_OUT9
TX_OUT10: J9.105 ; port TX_OUT10
TX_OUT11: J10.20 ; port TX_OUT11
TX_OUT12: J9.101 ; port TX_OUT12
TX_OUT13: J10.24 ; port TX_OUT13
TX_OUT14: J9.97 ; port TX_OUT14
TX_OUT15: J10.28 ; port TX_OUT15
TX_OUT16: J9.93 ; port TX_OUT16
TX_OUT17: J10.32 ; port TX_OUT17
TX_OUT18: J9.89 ; port TX_OUT18
TX_OUT19: J10.36 ; port TX_OUT19
TX_OUT20: J9.85 ; port TX_OUT20
TX_OUT21: J10.40 ; port TX_OUT21
TX_OUT22: J9.81 ; port TX_OUT22
TX_OUT23: J10.44 ; port TX_OUT23
TX_OUT24: J9.77 ; port TX_OUT24
TX_OUT25: J10.48 ; port TX_OUT25
TX_OUT26: J9.73 ; port TX_OUT26
TX_OUT27: J10.52 ; port TX_OUT27
TX_OUT28: J9.69 ; port TX_OUT28
TX_OUT29: J10.56 ; port TX_OUT29
TX_OUT30: J9.65 ; port TX_OUT30
TX_OUT31: J10.60 ; port TX_OUT31
TX_OUT32: J9.61 ; port TX_OUT32
TX_OUT33: J10.1 ; port TX_OUT33
TX_OUT34: J9.120 ; port TX_OUT34
TX_OUT35: J10.3 ; port TX_OUT35
TX_OUT36: J9.118 ; port TX_OUT36
TX_OUT37: J10.7 ; port TX_OUT37
TX_OUT38: J9.114 ; port TX_OUT38
TX_OUT39: J10.11 ; port TX_OUT39
TX_OUT40: J9.110 ; port TX_OUT40
TX_OUT41: J10.15 ; port TX_OUT41
TX_OUT42: J9.106 ; port TX_OUT42
TX_OUT43: J10.19 ; port TX_OUT43
TX_OUT44: J9.102 ; port TX_OUT44
TX_OUT45: J10.23 ; port TX_OUT45
TX_OUT46: J9.98 ; port TX_OUT46
TX_OUT47: J10.27 ; port TX_OUT47
TX_OUT48: J9.94 ; port TX_OUT48
TX_OUT49: J10.31 ; port TX_OUT49
TX_OUT50: J9.90 ; port TX_OUT50
TX_OUT51: J10.35 ; port TX_OUT51
TX_OUT52: J9.86 ; port TX_OUT52
TX_OUT53: J10.39 ; port TX_OUT53
TX_OUT54: J9.82 ; port TX_OUT54
TX_OUT55: J10.43 ; port TX_OUT55
TX_OUT56: J9.78 ; port TX_OUT56
TX_OUT57: J10.47 ; port TX_OUT57
TX_OUT58: J9.74 ; port TX_OUT58
TX_OUT59: J10.51 ; port TX_OUT59
TX_OUT60: J9.70 ; port TX_OUT60
TX_OUT61: J10.55 ; port TX_OUT61
TX_OUT62: J9.66 ; port TX_OUT62
TX_OUT63: J10.59 ; port TX_OUT63
TX_OUT64: J9.62 ; port TX_OUT64
TX_OUT65: J10.62 ; port TX_OUT65
TX_OUT66: J9.59 ; port TX_OUT66
TX_OUT67: J10.66 ; port TX_OUT67
TX_OUT68: J9.55 ; port TX_OUT68
TX_OUT69: J10.70 ; port TX_OUT69
TX_OUT70: J9.51 ; port TX_OUT70
TX_OUT71: J10.74 ; port TX_OUT71
TX_OUT72: J9.47 ; port TX_OUT72
TX_OUT73: J10.78 ; port TX_OUT73
TX_OUT74: J9.43 ; port TX_OUT74
TX_OUT75: J10.82 ; port TX_OUT75
TX_OUT76: J9.39 ; port TX_OUT76
TX_OUT77: J10.86 ; port TX_OUT77
TX_OUT78: J9.35 ; port TX_OUT78
TX_OUT79: J10.90 ; port TX_OUT79
TX_OUT80: J9.31 ; port TX_OUT80
TX_OUT81: J10.94 ; port TX_OUT81
TX_OUT82: J9.27 ; port TX_OUT82
TX_OUT83: J10.98 ; port TX_OUT83
TX_OUT84: J9.23 ; port TX_OUT84
TX_OUT85: J10.102 ; port TX_OUT85
TX_OUT86: J9.19 ; port TX_OUT86
TX_OUT87: J10.106 ; port TX_OUT87
TX_OUT88: J9.15 ; port TX_OUT88
TX_OUT89: J10.110 ; port TX_OUT89
TX_OUT90: J9.11 ; port TX_OUT90
TX_OUT91: J10.114 ; port TX_OUT91
TX_OUT92: J9.7 ; port TX_OUT92
TX_OUT93: J10.118 ; port TX_OUT93
TX_OUT94: J9.3 ; port TX_OUT94
TX_OUT95: J10.120 ; port TX_OUT95
TX_OUT96: J9.1 ; port TX_OUT96
TX_OUT97: J10.61 ; port TX_OUT97
TX_OUT98: J9.60 ; port TX_OUT98
TX_OUT99: J10.65 ; port TX_OUT99
TX_OUT100: J9.56 ; port TX_OUT100
TX_OUT101: J10.69 ; port TX_OUT101
TX_OUT102: J9.52 ; port TX_OUT102
TX_OUT103: J10.73 ; port TX_OUT103
TX_OUT104: J9.48 ; port TX_OUT104
TX_OUT105: J10.77 ; port TX_OUT105
TX_OUT106: J9.44 ; port TX_OUT106
TX_OUT107: J10.81 ; port TX_OUT107
TX_OUT108: J9.40 ; port TX_OUT108
TX_OUT109: J10.85 ; port TX_OUT109
TX_OUT110: J9.36 ; port TX_OUT110
TX_OUT111: J10.89 ; port TX_OUT111
TX_OUT112: J9.32 ; port TX_OUT112
TX_OUT113: J10.93 ; port TX_OUT113
TX_OUT114: J9.28 ; port TX_OUT114
TX_OUT115: J10.97 ; port TX_OUT115
TX_OUT116: J9.24 ; port TX_OUT116
TX_OUT117: J10.101 ; port TX_OUT117
TX_OUT118: J9.20 ; port TX_OUT118
TX_OUT119: J10.105 ; port TX_OUT119
TX_OUT120: J9.16 ; port TX_OUT120
TX_OUT121: J10.109 ; port TX_OUT121
TX_OUT122: J9.12 ; port TX_OUT122
TX_OUT123: J10.113 ; port TX_OUT123
TX_OUT124: J9.8 ; port TX_OUT124
TX_OUT125: J10.117 ; port TX_OUT125
TX_OUT126: J9.4 ; port TX_OUT126
TX_OUT127: J10.119 ; port TX_OUT127
TX_OUT128: J9.2 ; port TX_OUT128

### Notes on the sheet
- TX CONNECTOR
- Top
- Bottom

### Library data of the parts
J9 J10 = CMP-0860003-1: Receptacle, 0.5mm, 60x2, Gold, SMD; Manufacturer: Panasonic; Gender: Female; Row_Count: 2; Cert_UL: Y; Pitch_mm: 0.5; Voltage_V: 60V; RowSpacing_mm: 5; Current_A: 500mA; CompType: Socket Strip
